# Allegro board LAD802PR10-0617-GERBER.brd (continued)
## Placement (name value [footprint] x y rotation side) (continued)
RW1  0_0402_5%  [R_0402]  44.47 97.82 270 bottom
RW2  0_0402_5%  [R_0402]  43.58 97.82 270 bottom
RW3  0_0805_5%  [R_0805]  60.34 107.62 270 top
RW4  0_0402_5%  [R0402_0OHM]  55.84 109.64 270 top
RW5  0_0805_5%  [R_0805]  60.22 116.05 270 top
RW6  0_0402_5%  [R_0402]  53.93 106.37 90 top
RW8  100K_0402_5%  [R_0402]  52.14 107.21 0 top
RW9  0_0402_5%  [R0402_0OHM]  57.11 97.3 90 bottom
RX1  10K_0402_5%  [R_0402]  222.46 53.06 270 top
RX2  10K_0402_5%  [R_0402]  221.57 53.06 270 top
RX3  100K_0402_5%  [R_0402]  220.68 52.14 90 top
RX4  0_0402_5%  [R_0402-NPM]  219.12 42.95 90 bottom
RX5  4.99K_0402_1%  [R_0402]  208.44 38.06 180 bottom
RX6  0_0402_5%  [R_0402]  216.49 38.45 270 bottom
RX7  0_0402_5%  [R_0402-NPM]  218.23 42.95 90 bottom
RX8  0_0402_5%  [R_0402-NPM]  216.35 42.92 90 bottom
RX9  0_0402_5%  [R_0402-NPM]  217.24 42.92 90 bottom
RX10  10K_0402_5%  [R_0402]  218.45 45.93 90 top
RX11  3.3K_0402_5%  [R_0402]  210.27 36.52 90 bottom
RX12  0_0402_5%  [R_0402]  210.27 39.6 270 top
RX13  10K_0402_5%  [R_0402]  217.53 45.93 90 top
RX14  3.3K_0402_5%  [R_0402]  215.35 45.88 270 bottom
RX15  0_0402_5%  [R_0402]  215.35 45.88 270 top
RX16  4.7K_0402_5%  [R_0402]  211.79 45.88 270 bottom
RX17  4.7K_0402_5%  [R_0402]  211.79 45.88 270 top
RX18  4.7K_0402_5%  [R_0402]  211.16 36.52 90 bottom
RX19  4.7K_0402_5%  [R_0402]  211.16 39.6 270 top
RX20  4.7K_0402_5%  [R_0402]  212.68 45.88 270 bottom
RX21  4.7K_0402_5%  [R_0402]  212.68 45.88 270 top
RX22  4.7K_0402_5%  [R_0402]  213.57 45.88 270 bottom
RX23  4.7K_0402_5%  [R_0402]  213.57 45.88 270 top
RX24  4.7K_0402_5%  [R_0402]  214.46 45.88 270 bottom
RX25  4.7K_0402_5%  [R_0402]  214.46 45.88 270 top
RX26  4.7K_0402_5%  [R_0402]  212.05 36.52 90 bottom
RX27  4.7K_0402_5%  [R_0402]  212.05 39.6 270 top
RX28  4.7K_0402_5%  [R_0402]  212.93 36.52 90 bottom
RX29  4.7K_0402_5%  [R_0402]  212.93 39.6 270 top
RX30  4.7K_0402_5%  [R_0402]  213.82 36.52 90 bottom
RX31  4.7K_0402_5%  [R_0402]  213.82 39.6 270 top
RZ1  22.1K_0402_1%  [R_0402]  136.11 38.04 180 top
RZ2  0_0402_5%  [R_0402]  138.12 31.45 0 top
RZ3  49.9K_0402_1%  [R_0402]  139.15 35.05 90 top
RZ4  0_0603_5%  [R_0603]  135.11 43.52 180 top
RZ9  1M_0402_1%  [R_0402]  138.18 38.51 270 top
SW1  TST71-N-220-T170-S017_2P  [SW_TST71-N-220-T170-S017_2P]  155.1 111.08 180 top
TL1  NS14-1 LF 10/100 BASE-TX  [MHPC_NS681677_12P]  28.02 114.64 270 bottom
TP1  PAD  [TPC12]  119.08 59.39 0 top
TP2  PAD  [TPC12]  118.77 60.66 0 top
TP3  PAD  [TPC12]  95.97 67.14 180 bottom
TP4  PAD  [TPC12]  96.86 68.09 180 bottom
TP5  PAD  [TPC12]  106.57 64.53 0 top
TP6  PAD  [TPC12]  105.24 64.54 0 top
TP7  PAD  [TPC12]  126.96 78.63 180 bottom
TP8  PAD  [TPC12]  120.1 58.11 0 top
TP9  PAD  [TPC12]  121.75 57.55 0 top
TP10  PAD  [TPC12]  103.97 41.74 0 top
TP11  PAD  [TPC12]  95.97 42.44 180 bottom
TP12  PAD  [TPC12]  103.78 40.34 0 top
TP13  PAD  [TPC12]  107.21 38.93 0 top
TP14  PAD  [TPC12]  128.1 68.92 180 bottom
TP15  PAD  [TPC12]  125.88 64.66 180 bottom
TP16  PAD  [TPC12]  126.39 63.45 180 bottom
TP17  PAD  [TPC12]  124.99 63.45 180 bottom
TP18  PAD  [TPC12]  127.15 64.72 180 bottom
TP19  PAD  [TPC12]  99.94 77.15 180 bottom
TP20  PAD  [TPC12]  98.95 77.96 180 bottom
TP21  PAD  [TPC12]  97.3 76.21 180 bottom
TP22  PAD  [TPC12]  97.75 77.49 180 bottom
TP23  PAD  [TPC12]  107.97 39.96 0 top
TP24  PAD  [TPC12]  109.11 39.39 0 top
TP25  PAD  [TPC12]  105.18 36.02 0 top
TP26  PAD  [TPC12]  105.81 34.88 0 top
TP27  PAD  [TPC12]  97.87 31.77 180 bottom
TP28  PAD  [TPC12]  101.56 36.02 0 top
TP29  PAD  [TPC12]  100.86 34.44 0 top
TP30  PAD  [TPC12]  100.1 79.08 180 bottom
TP31  PAD  [TPC12]  98.8 79.35 180 bottom
TP32  PAD  [TPC12]  118.51 51.76 0 top
TP33  PAD  [TPC12]  108.16 51.76 0 top
TP34  PAD  [TPC12]  111.91 71.01 0 top
TP35  PAD  [TPC12]  111.91 69.66 0 top
TP36  PAD  [TPC12]  107.78 68.47 0 top
TP37  PAD  [TPC12]  108.35 66.95 0 top
TP38  PAD  [TPC12]  107.21 47.17 0 top
TP39  PAD  [TPC12]  107.34 45.42 0 top
TP40  PAD  [TPC12]  62.25 45.17 0 top
TP41  PAD  [TPC12]  64.16 44.09 0 top
TP42  PAD  [TPC12]  51.96 43.96 0 top
TP43  PAD  [TPC12]  46.69 45.8 0 top
TP44  PAD  [TPC12]  136.48 24.5 90 bottom
TP46  PAD  [TPC12]  200.3 46.06 180 bottom
TP47  PAD  [TPC12]  194.46 45.8 180 bottom
TP48  PAD  [TPC12]  38.18 117.24 180 bottom
TP49  PAD  [TPC12]  36.47 119.91 180 bottom
TP71  PAD  [TPC12]  157.75 18.05 180 bottom
TP74  PAD  [TPC12]  81.17 17.1 0 top
TP75  PAD  [TPC12]  106.76 41.55 0 top
TPC1  PAD  [TPC12]  128.35 65.17 270 bottom
TPC2  PAD  [TPC12]  125.56 67.07 180 bottom
TPC3  PAD  [TPC12]  129.69 65.17 180 bottom
TPC4  PAD  [TPC12]  126.77 65.99 180 bottom
TPC5  PAD  [TPC12]  121.97 66.76 0 top
TPC6  PAD  [TPC12]  125.62 68.41 180 bottom
TPC7  PAD  [TPC12]  127.15 31.96 180 bottom
TPC8  PAD  [TPC12]  99.84 28.28 180 bottom
TPC9  PAD  [TPC12]  102.32 28.21 180 bottom
TPC10  PAD  [TPC12]  126.31 77.31 180 bottom
TPC11  PAD  [TPC12]  124.94 77.28 180 bottom
TPC12  PAD  [TPC12]  126.49 76.01 180 bottom
TPC13  PAD  [TPC12]  125.94 79.46 180 bottom
TPC14  PAD  [TPC12]  120.73 76.79 0 top
TPC15  PAD  [TPC12]  122.88 77.22 180 bottom
TPC16  PAD  [TPC12]  123.35 79.55 180 bottom
TPC17  PAD  [TPC12]  124.63 79.46 180 bottom
TPC18  PAD  [TPC12]  119.59 70.19 0 top
TPC19  PAD  [TPC12]  120.99 70.12 0 top
TPC20  PAD  [TPC12]  122.47 78.44 180 bottom
TPC21  PAD  [TPC12]  120.58 79.52 180 bottom
TPC22  PAD  [TPC12]  121.61 77.07 180 bottom
TPC23  PAD  [TPC12]  121.93 79.63 180 bottom
TPC24  PAD  [TPC12]  119.65 78.5 180 bottom
TPC25  PAD  [TPC12]  120.9 78.19 180 bottom
TPC26  PAD  [TPC12]  119.82 75.82 180 bottom
TPC27  PAD  [TPC12]  120.24 77.06 180 bottom
TPC28  PAD  [TPC12]  120.1 72.33 0 top
TPC29  PAD  [TPC12]  121.56 72.28 0 top
TPC30  PAD  [TPC12]  129.56 68.78 180 bottom
TPC31  PAD  [TPC12]  124.86 65.99 180 bottom
TPC32  PAD  [TPC12]  80.6 29.74 0 top
TPC33  PAD  [TPC12]  130 79.33 180 bottom
TPS1  PAD  [TPC12]  123.21 28.02 180 bottom
TPS2  PAD  [TPC12]  105.75 40.28 0 top
TPS3  PAD  [TPC12]  136.67 27.01 0 top
TPS4  PAD  [TPC12]  98.45 41.74 180 bottom
TPS5  PAD  [TPC12]  97.11 41.67 180 bottom
TPS6  PAD  [TPC12]  105.53 43.46 0 top
TPS7  PAD  [TPC12]  90.06 24.47 0 top
TPS8  PAD  [TPC12]  153.27 109.24 0 top
TPS9  PAD  [TPC12]  152.25 104.31 0 top
TPS10  PAD  [TPC12]  132.48 39.2 180 bottom
U1  -  [SY6288C20AAC_SOT23-5]  224.84 26.38 0 bottom
U2  -  [NCT7718W_MSOP8]  112.22 107.46 90 bottom
UA1  ALC3246-CG_MQFN48_6X6  [ALC3246-CG_MQFN48_6X6-S]  29.59 23.01 270 top
UC1  SKL-U_BGA1356  [SKL-U_BGA_1356P-T]  123.48 33.54 270 bottom
UC2  -  [74AUP1G07GW_TSSOP5]  90.94 79.06 0 top
UC3  -  [W25Q128FVSIQ_SO8]  117.69 20.07 270 bottom
UC4  -  [SN74AHC1G08DCKR_SC70-5]  108.31 19.38 180 bottom
UC5  -  [SN74AHC1G08DCKR_SC70-5]  83.51 21.02 0 top
UC6  -  [74AUP1G07GW_TSSOP5]  88.14 19.17 270 top
UC7  -  [74AUP1G07GW_TSSOP5]  133.26 76.91 180 top
UC9  -  [SN74AHC1G08DCKR_SC70-5]  136.91 28.07 0 top
UE1  -  [MEC1404-NU-TR_VTQFP128_14X14]  140.33 18.78 0 bottom
UE2  -  [SN74LVC1G06DCKR_SC70-5]  153.6 22.84 180 top
UL1  RTL8106E-CG_QFN32_4X4  [RTL8106E-CG_QFN32_4X4-S]  36.15 114.73 180 bottom
UL3  -  [SY6288C20AAC_SOT23-5]  28.65 120.81 180 bottom
UU1  -  [SY6288D20AAC_SOT23-5]  8.58 27.39 270 bottom
UU3  -  [SY6288D20AAC_SOT23-5]  169.39 20.14 270 bottom
UX1  TPS22967DSGR_SON8_2X2  [TPS22967DSGR_SON8_2X2-S]  219.11 50.07 90 top
UX2  PS8713BTQFN24GTR2-A0_TQFN24_4X4  [SN65LVPE502CPRGER_VQFN24_4X4-S]  213.99 39.07 180 bottom
UZ1  TPS22967DSGR_SON8_2X2  [TPS22967DSGR_SON8_2X2-S]  132.81 37.52 0 top
UZ2  -  [TPS22961DNYR_WSON8]  137.07 33.45 90 top
UZ3  EM5209VF_DFN14_3X2  [EM5209VF_DFN14_3X2-S]  168.58 24.16 180 top
YC1  24MHZ_12PF_X3G024000DC1H  [Y_X3G024000DC1H_4P]  132.46 52.06 90 bottom
YC2  32.768KHZ_9PF_X1A000141000200  [Y_X1A000141000200_2P]  92.26 30.74 180 top
YE1  32.768KHZ_9PF_X1A000141000200  [Y_X1A000141000200_2P]  144.09 12.48 180 bottom
YL1  25MHZ_10PF_7V25000014  [Y_7V25000014_4P]  37.97 122.41 0 bottom
ZT1  PAD  [TPC12]  156.45 111.42 0 top
ZT2  PAD  [TPC12]  156.73 109.56 0 top
ZT3  PAD  [TPC12]  156.85 107.93 0 top
ZT4  PAD  [TPC12]  12.53 8.13 0 top
ZT5  PAD  [TPC12]  10.84 8.12 0 top
ZT6  PAD  [TPC12]  11.22 4.92 0 top
ZT7  PAD  [TPC12]  8.86 5.31 0 top
ZT8  PAD  [TPC12]  105.8 10.2 0 top
ZT9  PAD  [TPC12]  108.29 5.99 0 top
ZT10  PAD  [TPC12]  99.05 7.31 0 top
ZT11  PAD  [TPC12]  102.95 11.45 0 top
ZT12  PAD  [TPC12]  98.04 14.32 0 top
ZT13  PAD  [TPC12]  96.67 11.45 180 bottom
ZT14  PAD  [TPC12]  148.99 31.26 0 top
ZT15  PAD  [TPC12]  145.69 30.75 0 top
ZT16  PAD  [TPC12]  151.28 11.96 0 top
ZT17  PAD  [TPC12]  151.92 13.73 0 top
ZT18  PAD  [TPC12]  15.55 15.99 0 top
ZT19  PAD  [TPC12]  14.55 11.07 0 top
ZT20  PAD  [TPC12]  14.05 21.29 180 bottom
ZT21  PAD  [TPC12]  14.31 23.64 180 bottom
ZT22  PAD  [TPC12]  14.66 12.64 0 top
ZT23  PAD  [TPC12]  12.28 11.64 180 bottom
ZT24  PAD  [TPC12]  63.34 10.56 0 top
ZT25  PAD  [TPC12]  64.85 9.7 0 top
ZT26  PAD  [TPC12]  65.41 7.31 0 top
ZT27  PAD  [TPC12]  67.06 9.81 0 top
ZT28  PAD  [TPC12]  67.05 7.28 0 top
ZT29  PAD  [TPC12]  68.64 9.17 0 top
ZT30  PAD  [TPC12]  70.37 8.79 0 top
ZT31  PAD  [TPC12]  71.2 10.53 0 top
ZT32  PAD  [TPC12]  68.84 7.31 0 top
ZT33  PAD  [TPC12]  71.65 7.24 0 top
ZT34  PAD  [TPC12]  73.02 9.61 0 top
ZT35  PAD  [TPC12]  73.59 7.12 0 top
ZT36  PAD  [TPC12]  74.21 10.99 0 top
ZT37  PAD  [TPC12]  75.13 8.83 0 top
ZT38  PAD  [TPC12]  75.75 11.69 0 top
ZT39  PAD  [TPC12]  76.88 9.28 0 top
ZT40  PAD  [TPC12]  77.36 11.13 0 top
ZT41  PAD  [TPC12]  77.06 7.36 0 top
ZT42  PAD  [TPC12]  79.2 10.77 0 top
ZT43  PAD  [TPC12]  80.33 12.45 0 top
ZT44  PAD  [TPC12]  80.56 9.06 0 top
ZT45  PAD  [TPC12]  81.92 11.21 0 top
ZT46  PAD  [TPC12]  82.4 8.77 0 top
ZT47  PAD  [TPC12]  84.09 11.4 0 top
ZT48  PAD  [TPC12]  84.06 9.48 0 top
ZT49  PAD  [TPC12]  85.82 10.6 0 top
ZT50  PAD  [TPC12]  84.28 7.77 0 top
ZT51  PAD  [TPC12]  116.61 10.05 180 bottom
ZT52  PAD  [TPC12]  114.45 4.53 0 top
ZT53  PAD  [TPC12]  128.42 9.16 0 top
ZT54  PAD  [TPC12]  129.56 9.73 0 top
ZT55  PAD  [TPC12]  129.43 12.88 0 top
ZT56  PAD  [TPC12]  130.89 9.73 0 top
ZT57  PAD  [TPC12]  135.59 9.23 0 top
ZT58  PAD  [TPC12]  134.7 10.43 0 top
ZT59  PAD  [TPC12]  93.05 9.29 180 bottom
ZT60  PAD  [TPC12]  126.89 9.16 0 top
ZT61  PAD  [TPC12]  120.86 9.48 180 bottom
ZT62  PAD  [TPC12]  28.02 81.45 0 top
ZT63  PAD  [TPC12]  58.36 98.21 180 bottom

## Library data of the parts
C1-C3 C5-C11 C13 C14 C16-C19 C21 C23-C27 C32-C34 CA2 CA4 CA6 CA7 CA10 CA14 CA16 CA17 CA27-CA31 CA34-CA37 CC1-CC35 CC39-CC58 CC60-CC73 CC75 CC78 CC79 CC82 CC85-CC90 CD3-CD5 CD9 CD11-CD18 CD28-CD31 CD35 CD36 CD39 CD41-CD48 CD58 CD59 CE1-CE4 CE6-CE23 CE25-CE33 CI1-CI9 CL1-CL6 CL8-CL12 CL14 CS1-CS6 CS9-CS14 CS16-CS19 CU1-CU7 CU17-CU19 CW1-CW4 CW7-CW9 CX1-CX13 CZ1-CZ12 CZ21-CZ25 EC2201-EC2216 EC2225 EC2226 EC2229 EC2230 EC2301 EC2302 EC2901 EC2902 EC3001 EC3002 EC3201 EC3202 PC1-PC4 PC7 PC8 PC14 PC16 PC100 PC102 PC103 PC113-PC116 PC127 PC128 PC130-PC133 PC200-PC203 PC207 PC208 PC210 PC213 PC214 PC230 PC231 PC301 PC302 PC304-PC307 PC309 PC320 PC321 PC502-PC504 PC601 PC602 PC605 PC611 PC613 PC614 PC616-PC621 PC624-PC633 PC635-PC647 PC649-PC655 PC659-PC661 PC663 PC666-PC669 PC671 PC674 PC677 PC679-PC681 PC685-PC688 PC691-PC695 PC705 PC708 PC711 PC721 PC742 PC744 PC747-PC749 PC751-PC753 PC765 PC768 PC769 PC777 PC779-PC781 PC790 PC801 PC803 PC805 PC1201 PC1202 PC1204 PC1205 PC1209-PC1212 = C_0402
C4 C15 C20 C22 CA1 CA3 CA5 CA11-CA13 CA15 CA20-CA26 CA32 CA33 CC36-CC38 CC76 CC77 CC80 CC81 CC83 CC84 CD1 CD2 CD6-CD8 CD10 CD19-CD26 CD32-CD34 CD37 CD38 CD40 CD49-CD56 CE5 CE24 CL7 CW5 CW6 EC2217 EC2218 PC111 PC112 PC119 PC125 PC126 PC204 PC209 PC215-PC220 PC308 PC310-PC313 PC501 PC505-PC507 PC603 PC604 PC622 PC662 PC670 PC678 PC750 PC757 PC767 PC1001-PC1029 PC1057-PC1061 PC1064-PC1082 PC1129-PC1146 PC1154-PC1156 PC1158 PC1159 PC1161-PC1163 PC1170-PC1184 PC1203 PC1206-PC1208 PC1221-PC1224 = C_0603
C30 CC59 CC74 CS7 CS15 CU8 CU9 CU20 CU21 PC104-PC110 PC117 PC118 PC120-PC124 PC205 PC206 PC211 PC212 PC303 PC608 PC612 PC656-PC658 PC664 PC665 PC672 PC673 PC760-PC764 PC766 PC775 PC776 PC778 PC802 PC804 = C_0805
CD27 CD57 = C_D2
CL13 CU10 CU22 = C_1206
D1 = BAS40C_SOT23-3
D2 D5 D6 = RB551V-30_SOD323-2
D3 D4 DA3 = BAT54C-7-F_SOT23-3
D8 PD102 = SDMK0340L-7-F_SOD323-2
DA1 DA2 = AZ5125-02SPR7G_SOT23-3
DA4 = L03ESDL5V0CC3-2_SOT23-3
DA5 = AZ5123-02SPR7G_SOT23-3
DA6 = PESD5V0U2BT_SOT23-3
DE1 = AZ5125-01HPR7G_SOD523-2
DX1 = IP4292CZ10-TBR_XSON10_2P5X1
DX2 DX3 DZ1-DZ5 = RB751S40T1G_SOD523-2
ED2901 = AZ5725-01F_DFN2
EU2601 EU2603 EU3101 = L05ESDL5V0NA-4_SLP2510P8-10-9
EU2602 EU2604 = AZC199-02SPR7G_SOT23-3
EU3501 = TVWDF1004AD0_DFN9
F1 F2 = F_SMD1812P110TF-24
F3 = F_MF-NSMF050-2
FD1-FD4 = FIDUCIAL_C40M80
FI1 = F_1206L150PR
H1-H5 H21 = H_3P0-G
H6 = H_5P6N
H7 = H_3P0N
H11 = H_3P2
H12 = H_3P2X2P6
HCPU1 HCPU4 = H_3P7X4P3
HCPU2 = H_3P9
HCPU3 = H_3P7
J3D1 = ACES_50463-0104A-001_10P
JCMOS1 = SHORTPADS: User Part Number: PART#
JDB1 JDEG1 = JXT_FP241AH-010GAAM_10P
JDIMM1 = DEREN_40-42271-26001RHF_260P-T
JDIMM2 = DEREN_40-42261-26001RHF_260P-T
JEDP1 = ACES_51540-04001-P01_40P
JFAN1 JSPK1 = JXT_WB247H-004S10M_4P
JHDD1 = ACES_51625-01201-001_12P
JHDMI1 = CONCR_099AKAC19NBLCNF_19P
JHP1 = YUQIU_PJ753-F07J1BE-B_7P-T
JIOB1 = ACES_51524-0160N-001_16P
JKB1 = STARC_132C30-100020-A2-R_30P
JKBBL1 = ACES_51575-00401-001_4P-T
JLAN1 = SANTA_130460-N_8P-T
JLED1 = ACES_51524-0040N-001_4P
JODD1 = ACES_50673-0120N-001_12P-T
JP1 JP9 JP12 JP13 PJP105 PJP106 PJP203 PJP206 PJP301 PJP501 PJP502 PJP801 PJP802 PJP1201 PJP1202 = JUMP_43X79
JP2 JP3 JP10 JP11 PJP603 = JUMP_43X39
JP4 JP5 PJP102 PJP103 PJP200 PJP302 PJP602 PJP701 = JUMP_43X118
JPWR1 = JXT_FP226H-006S1BM_6P
JRTC1 = ACES_50271-0020N-001_2P
JSSD1 = ACES_50406-03071-001_30P
JTP1 = JXT_FP202DH-008M10M_8P
JUSB1 JUSB2 = ACON_TARA4-9K1311_9P
JWLAN1 = LCN_DAN05-67406-0100_67P
L1 L2 = MURAT_BLM15BD601SN1D_2P
L3 LU1 LU4 LU7 LU8 = INPAQ_MCM1012B900F06BP_4P
L4 LW1 = INPAQ_MCM1012B900F06BP_4P-NPM
L5 = MURAT_BLM15PX221SN1D_2P
LI1-LI4 LU2 LU3 LU5 LU6 = INPAQ_HCM1012GH900BP_4P-NPM
LX1 LX2 = TAIYO_MCF12102G900-T_4P
PBATT1 = ACES_50458-01001-P01_10P-T
PC606 PC690 = C_25CL33LD
PC1030-PC1056 PC1083-PC1099 PC1125 PC1126 PC1147-PC1153 PC1164 = C_0201
PC1062 PC1063 PC1101 PC1127 PC1128 = C_5X4P5
PD2-PD4 = TVNST52302AB0_SOT523-3
PD5 PD6 = BAV99W_SC70-3
PD704 = LRB715FT1G_SOT323-3
PH601-PH605 PR2-PR4 PR6-PR13 PR15 PR16 PR18 PR20 PR28 PR29 PR31-PR33 PR102 PR103 PR107-PR110 PR113-PR115 PR117 PR118 PR122 PR204 PR205 PR207-PR209 PR302 PR305 PR308-PR310 PR502-PR505 PR601 PR604 PR605 PR608 PR610-PR613 PR615 PR617 PR618 PR621-PR623 PR626 PR628-PR654 PR656 PR657 PR662 PR664 PR666 PR668 PR670 PR673 PR675 PR677 PR678 PR680 PR681 PR727 PR729 PR731 PR732 PR737 PR738 PR740-PR742 PR745 PR749-PR757 PR760 PR762-PR764 PR774 PR777 PR781 PR790 PR791 PR801 PR802 PR1201 PR1202 PR1204-PR1207 R1 R2 R5 R6 R9 R10 R19-R35 R38-R43 R45-R50 R53 R56 R57 RA3 RA7-RA12 RA23-RA34 RA41 RA42 RC1-RC16 RC18-RC47 RC51-RC70 RC72-RC78 RC80-RC82 RC84-RC96 RC100 RC102-RC105 RC108-RC115 RC117-RC134 RC136-RC148 RC150-RC160 RC164 RC175-RC182 RC187-RC189 RC192 RD1-RD3 RD7 RD9-RD13 RD15 RD17 RD19-RD24 RE1 RE3 RE4 RE6 RE8-RE21 RE23-RE27 RE29 RE30 RE32-RE35 RE38 RE40 RE41 RE43-RE49 RE51-RE59 RI1-RI16 RL1-RL4 RL6 RL7 RL16 RS1 RU3-RU6 RU9-RU12 RW1 RW2 RW6 RW8 RX1-RX3 RX5 RX6 RX10-RX31 RZ1-RZ3 RZ9 = R_0402
PJP1-PJP3 = JUMP_43X79-NPM
PJP601 = JUMP_43X118-NPM
PJPDC1 = ACES_50458-00601-001_6P-T
PL1 PL3 PL4 PL602 = 5A_Z150_1210_2P
PL2 = MURAT_BLM15AG102SN1D_2P
PL100 PL101 PL200 PL700 = L_7X7X3_M_2P
PL102 PL103 PL201 PL302 PL606 PL1202 = 5A_Z150_1210_2P-NPM
PL301 PL501 PL1201 = L_5X5X3_M_2P
PL601 = L_5X5X3_M
PL603-PL605 = L_7X7X4_M
PL704 = L_5X5X3_M_2P-NPM
PQ1 PQ2 = 2N7002DW-T-R7_SOT363-6
PQ3 PQ709 PQ712 = L2N7002WT1G_SC70-3
PQ5 = RHU002N06_SOT323-3
PQ6 = FDV301N_NL_SOT23-3
PQ201 PQ601 = AON7934_DFN3X3A8-10
PQ704 PQ708 = SIS412DN-T1-GE3_POWERPAK8-5
PQ710 = LMUN5113T1G_SOT323-3
PQ711 = LTC015EUBFS8TL_UMT3F
PQ717 PQ718 PQ740 = MDU1512RH_POWERDFN56-8-5
PQ720 PQ721 = RUM002N02GT2L_VMT3
PR5 PR106 PR112 PR203 PR307 PR506 PR627 PR663 PR669 PR676 PR743 PR766 PR1208 = R_1206
PR100 PR111 PR200 PR306 PR761 PR771 PR773 R55 RA4 RA39 RC17 RC161-RC163 RC169-RC171 RC173 RC174 RE2 RE7 RE50 RL5 = R0603_0OHM
PR116 PR120 PR121 PR201 PR202 PR301 PR303 PR304 PR501 PR602 PR603 PR606 PR607 PR609 PR616 PR620 PR625 PR655 PR659 PR671 PR679 PR769 PR770 PR772 PR775 PR776 PR778 PR779 PR803 R8 RA2 RA5 RA6 RA17 RA18 RA36 RA37 RA40 RC83 RC97 RC99 RC106 RC107 RD4-RD6 RD8 RD14 RD16 RD18 RE22 RE28 RE37 RE42 RE60 RE61 RE63 RE64 RL12 RL13 RW4 RW9 = R0402_0OHM
PR206 PR210 PR619 PR624 PR660 PR661 PR665 PR667 PR672 PR674 PR780 PR1203 R11-R13 R16 R36 R37 R44 RC149 RL14 RL15 RZ4 = R_0603
PR703 PR765 = R_1206_4P
PU100 = SY8286BRAC_QFN20_3X3-S
PU102 = SY8286CRAC_QFN20_3X3-S
PU200 = RT8207PGQW_WQFN20_3X3-S
PU300 = SY8286RAC_QFN20_3X3-S
PU500 = SY8033BDBC_DFN10_3X3-S
PU602 = ISL62883CHRTZ-T_TQFN40_5X5-S
PU603-PU605 = AOZ5019QI_QFN23_5X3P5
PU606 = ISL95808HRZ-TS2378_DFN8_2X2-S
PU703 = ISL95520HRZ-T_QFN32_4X4-S
PU800 = RT904225GSP_SO8
PU1200 = NB681GD-Z_QFN13_2X3
Q1 Q5 Q12 Q13 QC2 QI1 = 2N7002K_SOT23-3
Q2 Q10 Q11 QC1 QI2 = DMN66D0LDW-7_SOT363-6
Q3 Q4 Q7 Q15 = DDTA144VCA-7-F_SOT23-3
Q6 Q8 Q9 Q16 QA1 = LN2306LT1G_SOT23-3
Q14 = LMBT3904LT1G_SOT23-3
QI3 = SSM3K7002FU_SC70-3
R3 R54 RW3 RW5 = R_0805
R17 R18 RU1 RU2 RU7 RU8 RU13-RU16 RX4 RX7-RX9 = R_0402-NPM
R51 RA1 RA22 = R0805_0OHM
RA13-RA16 = MURAT_BLM15PD600SN1D_2P
RA35 RA38 = MURAT_BLM15PX330SN1D_2P
RP1 RP2 RPC1 RPE1-RPE6 RPI1 RPI2 = RP_0804_8P4R
SW1 = SW_TST71-N-220-T170-S017_2P
TL1 = MHPC_NS681677_12P
TP1-TP44 TP46-TP49 TP71 TP74 TP75 TPC1-TPC33 TPS1-TPS10 ZT1-ZT63 = TPC12
U1 UL3 = SY6288C20AAC_SOT23-5
U2 = NCT7718W_MSOP8
UA1 = ALC3246-CG_MQFN48_6X6-S
UC1 = SKL-U_BGA_1356P-T
UC2 UC6 UC7 = 74AUP1G07GW_TSSOP5
UC3 = W25Q128FVSIQ_SO8
UC4 UC5 UC9 = SN74AHC1G08DCKR_SC70-5
UE1 = MEC1404-NU-TR_VTQFP128_14X14
UE2 = SN74LVC1G06DCKR_SC70-5
UL1 = RTL8106E-CG_QFN32_4X4-S
UU1 UU3 = SY6288D20AAC_SOT23-5
UX1 UZ1 = TPS22967DSGR_SON8_2X2-S
UX2 = SN65LVPE502CPRGER_VQFN24_4X4-S
UZ2 = TPS22961DNYR_WSON8
UZ3 = EM5209VF_DFN14_3X2-S
YC1 = Y_X3G024000DC1H_4P
YC2 YE1 = Y_X1A000141000200_2P
YL1 = Y_7V25000014_4P

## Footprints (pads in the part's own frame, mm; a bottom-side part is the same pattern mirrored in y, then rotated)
2N7002DW-T-R7_SOT363-6
  oval 0.381x1.397 smd: 1(0,0) 2(0.65,0) 3(1.3,0) 4(1.3,1.725) 5(0.65,1.725) 6(0,1.725)
2N7002K_SOT23-3
  oval 1.016x1.524 smd: 1(0,0) 2(0.965,2.083) 3(-0.965,2.083)
5A_Z150_1210_2P
  rect 0.991x2.997 smd: 1(0,0) 2(2.7,0)
5A_Z150_1210_2P-NPM
  rect 0.991x2.997 smd: 1(0,0) 2(2.7,0)
74AUP1G07GW_TSSOP5
  oval 0.381x1.346 smd: 1(0,0) 2(0.65,0) 3(1.3,0) 4(1.3,1.79) 5(0,1.79)
ACES_50271-0020N-001_2P
  oval 0.787x1.6 smd: 1(0,0) 2(1.25,0)
  rect 2.108x2.997 smd: 3(3.8,-2.9) 4(-2.55,-2.9)
ACES_50406-03071-001_30P
  oval 0.254x1.295 smd: 1(0,0) 2(0.5,0) 3(1,0) 4(1.5,0) 5(2,0) 6(2.5,0) 7(3,0) 8(3.5,0) 9(4,0) 10(4.5,0) 11(5,0) 12(5.5,0) 13(6,0) 14(6.5,0) 15(7,0) 16(7.5,0) 17(8,0) 18(8.5,0) 19(9,0) 20(9.5,0) 21(10,0) 22(10.5,0) 23(11,0) 24(11.5,0) 25(12,0) 26(12.5,0) 27(13,0) 28(13.5,0) 29(14,0) 30(14.5,0)
  rect 1.194x2.692 smd: 31(16.9,1.95) 35(-2.4,1.95)
  rect 2.311x1.295 smd: 32(13.65,3.9) 33(7.25,3.9) 34(0.85,3.9)
ACES_50458-00601-001_6P-T
  oval 0.559x1.6 smd: 1(0,0) 2(2,0) 3(4,0) 4(6,0) 5(8,0) 6(10,0)
  rect 1.295x2.057 smd: 7(-3.1,-5.175) 8(13.1,-5.175)
ACES_50458-01001-P01_10P-T
  oval 0.559x1.803 smd: 1(0,0) 2(2,0) 3(4,0) 4(6,0) 5(8,0) 6(10,0) 7(12,0) 8(14,0) 9(16,0) 10(18,0)
  rect 1.295x2.057 smd: 11(-3.1,-5.275) 12(21.1,-5.275)
ACES_50463-0104A-001_10P
  oval 0.203x1.194 smd: 1(0,0) 2(-0.4,0) 3(-0.8,0) 4(-1.2,0) 5(-1.6,0) 6(-2,0) 7(-2.4,0) 8(-2.8,0) 9(-3.2,0) 10(-3.6,0)
  rect 0.889x2.007 smd: 11(-5.85,-1.37) 12(2.25,-1.37)
ACES_50673-0120N-001_12P-T
  oval 0.61x1.499 smd: 1(0,0) 3(-1,0) 5(-2,0) 7(-3,0) 9(-4,0) 11(-5,0) 13(-6,0) 15(-7,0) 17(-8,0) 19(-9,0) 21(-10,0) 23(-11,0)
  oval 0.61x1.194 smd: 2(0,2.85) 4(-1,2.85) 6(-2,2.85) 8(-3,2.85) 10(-4,2.85) 12(-5,2.85) 14(-6,2.85) 16(-7,2.85) 18(-8,2.85) 20(-9,2.85) 22(-10,2.85) 24(-11,2.85)
  rect 1.702x2.311 smd: 25(-13.25,1.425) 26(2.25,1.425)
ACES_51524-0040N-001_4P
  oval 0.61x1.448 smd: 1(0,0) 2(1,0) 3(2,0) 4(3,0)
  rect 2.489x2.21 smd: 5(-3,-3.125) 6(6,-3.125)
ACES_51524-0160N-001_16P
  oval 0.61x1.295 smd: 1(0,0) 2(1,0) 3(2,0) 4(3,0) 5(4,0) 6(5,0) 7(6,0) 8(7,0) 9(8,0) 10(9,0) 11(10,0) 12(11,0) 13(12,0) 14(13,0) 15(14,0) 16(15,0)
  rect 2.159x2.21 smd: 17(-2.825,-3.05) 18(17.825,-3.05)
ACES_51540-04001-P01_40P
  oval 0.305x1.092 smd: 1(0,0) 2(0.5,0) 3(1,0) 4(1.5,0) 5(2,0) 6(2.5,0) 7(3,0) 8(3.5,0) 9(4,0) 10(4.5,0) 11(5,0) 12(5.5,0) 13(6,0) 14(6.5,0) 15(7,0) 16(7.5,0) 17(8,0) 18(8.5,0) 19(9,0) 20(9.5,0) 21(10,0) 22(10.5,0) 23(11,0) 24(11.5,0) 25(12,0) 26(12.5,0) 27(13,0) 28(13.5,0) 29(14,0) 30(14.5,0) 31(15,0) 32(15.5,0) 33(16,0) 34(16.5,0) 35(17,0) 36(17.5,0) 37(18,0) 38(18.5,0) 39(19,0) 40(19.5,0)
  rect 0.787x2.489 smd: 41(21.2,-3.6) 42(-1.7,-3.6)
ACES_51575-00401-001_4P-T
  oval 0.406x1.194 smd: 1(0,0) 2(1,0) 3(2,0) 4(3,0)
  rect 0.787x2.007 smd: 5(-2.2,-3.4) 6(5.2,-3.4)
ACES_51625-01201-001_12P
  oval 0.305x1.092 smd: 1(0,0) 2(0.5,0) 3(1,0) 4(1.5,0) 5(2,0) 6(2.5,0) 7(3,0) 8(3.5,0) 9(4,0) 10(4.5,0) 11(5,0) 12(5.5,0)
  rect 0.991x2.489 smd: 13(-1.8,-3.6) 14(7.3,-3.6)
ACON_TARA4-9K1311_9P
  round 1.194 hole 0.711: 1(0,0) 2(-2.5,0) 3(-4.5,0) 4(-7,0) 5(-7.5,-1.5) 6(-5.5,-1.5) 7(-3.5,-1.5) 8(-1.5,-1.5) 9(0.5,-1.5)
  oval 1.397x2.591 hole 0.787x2.007: 10(-11.35,-1.59) 13(4.35,-1.59)
  oval 1.397x2.388 hole 0.787x1.803: 11(-11.35,-9.09) 12(4.35,-9.09)
ALC3246-CG_MQFN48_6X6-S
  oval 0.889x0.203 smd: 1(0,0) 2(0,-0.4) 3(0,-0.8) 4(0,-1.2) 5(0,-1.6) 6(0,-2) 7(0,-2.4) 8(0,-2.8) 9(0,-3.2) 10(0,-3.6) 11(0,-4) 12(0,-4.4) 25(6.1,-4.4) 26(6.1,-4) 27(6.1,-3.6) 28(6.1,-3.2) 29(6.1,-2.8) 30(6.1,-2.4) 31(6.1,-2) 32(6.1,-1.6) 33(6.1,-1.2) 34(6.1,-0.8) 35(6.1,-0.4) 36(6.1,0)
  oval 0.203x0.889 smd: 13(0.85,-5.25) 14(1.25,-5.25) 15(1.65,-5.25) 16(2.05,-5.25) 17(2.45,-5.25) 18(2.85,-5.25) 19(3.25,-5.25) 20(3.65,-5.25) 21(4.05,-5.25) 22(4.45,-5.25) 23(4.85,-5.25) 24(5.25,-5.25) 37(5.25,0.85) 38(4.85,0.85) 39(4.45,0.85) 40(4.05,0.85) 41(3.65,0.85) 42(3.25,0.85) 43(2.85,0.85) 44(2.45,0.85) 45(2.05,0.85) 46(1.65,0.85) 47(1.25,0.85) 48(0.85,0.85)
  rect 4.394x4.394 smd: 49(3.05,-2.2)
AON7934_DFN3X3A8-10
  oval 0.457x0.508 smd: 1(0,0) 2(0.65,0) 3(1.3,0) 4(1.95,0) 5(1.95,2.76) 6(1.3,2.76) 7(0.65,2.76) 8(0,2.76)
  rect 2.54x1.041 smd: 9(0.975,1.813)
  rect 2.54x0.559 smd: 10(0.975,0.708)
AOZ5019QI_QFN23_5X3P5
  oval 0.254x0.762 smd: 1(0,0) 2(0.5,0) 3(1,0) 4(1.5,0) 5(2,0)
  rect 3.175x1.524 smd: 6(1.475,1.335)
  custom 0.588x0.588 smd: 7(1.005,2.425)
  rect 1.956x0.864 smd: 8(1.255,4.787)
  oval 0.762x0.254 smd: 9(-0.67,2.925) 10(-0.67,1.925) 11(-0.67,1.425) 12(-0.67,0.925) 13(-0.67,0.425)
AZ5123-02SPR7G_SOT23-3
  oval 1.016x1.524 smd: 1(0,0) 2(0.965,2.083) 3(-0.965,2.083)
AZ5125-01HPR7G_SOD523-2
  rect 0.61x0.787 smd: 1(0,0) 2(1.5,0)
AZ5125-02SPR7G_SOT23-3
  oval 1.016x1.524 smd: 1(0,0) 2(0.965,2.083) 3(-0.965,2.083)
AZ5725-01F_DFN2
  rect 0.559x0.61 smd: 1(0,0) 2(0.85,0)
AZC199-02SPR7G_SOT23-3
  oval 1.016x1.524 smd: 1(0,0) 2(0.965,2.083) 3(-0.965,2.083)
BAS40C_SOT23-3
  oval 1.016x1.524 smd: 1(0,0) 2(0.965,2.083) 3(-0.965,2.083)
BAT54C-7-F_SOT23-3
  oval 1.016x1.524 smd: 1(0,0) 2(0.965,2.083) 3(-0.965,2.083)
BAV99W_SC70-3
  oval 0.508x0.559 smd: 1(0,0) 2(-0.65,-1.85) 3(0.65,-1.85)
C_5X4P5
  oval 2.997x1.6 smd: 1(0,0) 2(-4.4,0)
C_25CL33LD
  oval 3.607x1.803 smd: 1(0,0) 2(5.4,0)
C_0201
  rect 0.381x0.356 smd: 1(0,0) 2(0.584,0)
C_0402
  rect 0.508x0.559 smd: 1(0,0) 2(0.914,0)
C_0603
  rect 0.635x0.889 smd: 1(0,0) 2(1.397,0)
C_0805
  rect 0.813x1.397 smd: 1(0,0) 2(1.702,0)
C_1206
  rect 1.016x1.651 smd: 1(0,0) 2(2.667,0)
C_D2
  rect 2.388x2.794 smd: 1(0,0) 2(6.4,0)
CONCR_099AKAC19NBLCNF_19P
  round 0.813 hole 0.559: 1(0,0) 2(0.5,1.55) 3(1,0) 4(1.5,1.55) 5(2,0) 6(2.5,1.55) 7(3,0) 8(3.5,1.55) 9(4,0) 10(4.5,1.55) 11(5,0) 12(5.5,1.55) 13(6,0) 14(6.5,1.55) 15(7,0) 16(7.5,1.55) 17(8,0) 18(8.5,1.55) 19(9,0)
  oval 1.499x2.21 hole 0.889x1.6: 20(-2.75,1.7) 21(-4.65,-6.5) 22(11.75,1.7) 23(13.65,-7.75)
DDTA144VCA-7-F_SOT23-3
  oval 1.016x1.524 smd: 1(0,0) 2(0.965,2.083) 3(-0.965,2.083)
DEREN_40-42261-26001RHF_260P-T
  round 1.092 hole 1.092 unplated: (-67.775,-4.1)
  round 1.6 hole 1.6 unplated: (1.025,-4.1)
  oval 0.305x1.753 smd: 1(0,0) 2(-0.25,-8.2) 3(-0.5,0) 4(-0.75,-8.2) 5(-1,0) 6(-1.25,-8.2) 7(-1.5,0) 8(-1.75,-8.2) 9(-2,0) 10(-2.25,-8.2) 11(-2.5,0) 12(-2.75,-8.2) 13(-3,0) 14(-3.25,-8.2) 15(-3.5,0) 16(-3.75,-8.2) 17(-4,0) 18(-4.25,-8.2) 19(-4.5,0) 20(-4.75,-8.2) 21(-5,0) 22(-5.25,-8.2) 23(-5.5,0) 24(-5.75,-8.2) 25(-6,0) 26(-6.25,-8.2) 27(-6.5,0) 28(-6.75,-8.2) 29(-7,0) 30(-7.25,-8.2) 31(-7.5,0) 32(-7.75,-8.2) 33(-8,0) 34(-8.25,-8.2) 35(-8.5,0) 36(-8.75,-8.2) 37(-9,0) 38(-9.25,-8.2) 39(-9.5,0) 40(-9.75,-8.2) 41(-10,0) 42(-10.25,-8.2) 43(-10.5,0) 44(-10.75,-8.2) 45(-11,0) 46(-11.25,-8.2) 47(-11.5,0) 48(-11.75,-8.2) 49(-12,0) 50(-12.25,-8.2) 51(-12.5,0) 52(-12.75,-8.2) 53(-13,0) 54(-13.25,-8.2) 55(-13.5,0) 56(-13.75,-8.2) 57(-14,0) 58(-14.25,-8.2) 59(-14.5,0) 60(-14.75,-8.2) 61(-15,0) 62(-15.25,-8.2) 63(-15.5,0) 64(-15.75,-8.2) 65(-16,0) 66(-16.25,-8.2) 67(-16.5,0) 68(-16.75,-8.2) 69(-17,0) 70(-17.25,-8.2) 71(-17.5,0) 72(-17.75,-8.2) 73(-18,0) 74(-18.25,-8.2) 75(-18.5,0) 76(-18.75,-8.2) 77(-19,0) 78(-19.25,-8.2) 79(-19.5,0) 80(-19.75,-8.2) 81(-20,0) 82(-20.25,-8.2) 83(-20.5,0) 84(-20.75,-8.2) 85(-21,0) 86(-21.25,-8.2) 87(-21.5,0) 88(-21.75,-8.2) 89(-22,0) 90(-22.25,-8.2) 91(-22.5,0) 92(-22.75,-8.2) 93(-23,0) 94(-23.25,-8.2) 95(-23.5,0) 96(-23.75,-8.2) 97(-24,0) 98(-24.25,-8.2) 99(-24.5,0) 100(-24.75,-8.2) 101(-25,0) 102(-25.25,-8.2) 103(-25.5,0) 104(-25.75,-8.2) 105(-26,0) 106(-26.25,-8.2) 107(-26.5,0) 108(-26.75,-8.2) 109(-27,0) 110(-27.25,-8.2) 111(-27.5,0) 112(-27.75,-8.2) 113(-28,0) 114(-28.25,-8.2) 115(-28.5,0) 116(-28.75,-8.2) 117(-29,0) 118(-29.25,-8.2) 119(-29.5,0) 120(-29.75,-8.2) 121(-30,0) 122(-30.25,-8.2) 123(-30.5,0) 124(-30.75,-8.2) 125(-31,0) 126(-31.25,-8.2) 127(-31.5,0) 128(-31.75,-8.2) 129(-32,0) 130(-32.25,-8.2) 131(-32.5,0) 132(-32.75,-8.2) 133(-33,0) 134(-33.25,-8.2) 135(-33.5,0) 136(-33.75,-8.2) 137(-34,0) 138(-34.25,-8.2) 139(-34.5,0) 140(-34.75,-8.2) 141(-35,0) 142(-35.25,-8.2) 143(-35.5,0) 144(-35.75,-8.2) 145(-38,0) 146(-38.25,-8.2) 147(-38.5,0) 148(-38.75,-8.2) 149(-39,0) 150(-39.25,-8.2) 151(-39.5,0) 152(-39.75,-8.2) 153(-40,0) 154(-40.25,-8.2) 155(-40.5,0) 156(-40.75,-8.2) 157(-41,0) 158(-41.25,-8.2) 159(-41.5,0) 160(-41.75,-8.2) 161(-42,0) 162(-42.25,-8.2) 163(-42.5,0) 164(-42.75,-8.2) 165(-43,0) 166(-43.25,-8.2) 167(-43.5,0) 168(-43.75,-8.2) 169(-44,0) 170(-44.25,-8.2) 171(-44.5,0) 172(-44.75,-8.2) 173(-45,0) 174(-45.25,-8.2) 175(-45.5,0) 176(-45.75,-8.2) 177(-46,0) 178(-46.25,-8.2) 179(-46.5,0) 180(-46.75,-8.2) 181(-47,0) 182(-47.25,-8.2) 183(-47.5,0) 184(-47.75,-8.2) 185(-48,0) 186(-48.25,-8.2) 187(-48.5,0) 188(-48.75,-8.2) 189(-49,0) 190(-49.25,-8.2) 191(-49.5,0) 192(-49.75,-8.2) 193(-50,0) 194(-50.25,-8.2) 195(-50.5,0) 196(-50.75,-8.2) 197(-51,0) 198(-51.25,-8.2) 199(-51.5,0) 200(-51.75,-8.2) 201(-52,0) 202(-52.25,-8.2) 203(-52.5,0) 204(-52.75,-8.2) 205(-53,0) 206(-53.25,-8.2) 207(-53.5,0) 208(-53.75,-8.2) 209(-54,0) 210(-54.25,-8.2) 211(-54.5,0) 212(-54.75,-8.2) 213(-55,0) 214(-55.25,-8.2) 215(-55.5,0) 216(-55.75,-8.2) 217(-56,0) 218(-56.25,-8.2) 219(-56.5,0) 220(-56.75,-8.2) 221(-57,0) 222(-57.25,-8.2) 223(-57.5,0) 224(-57.75,-8.2) 225(-58,0) 226(-58.25,-8.2) 227(-58.5,0) 228(-58.75,-8.2) 229(-59,0) 230(-59.25,-8.2) 231(-59.5,0) 232(-59.75,-8.2) 233(-60,0) 234(-60.25,-8.2) 235(-60.5,0) 236(-60.75,-8.2) 237(-61,0) 238(-61.25,-8.2) 239(-61.5,0) 240(-61.75,-8.2) 241(-62,0) 242(-62.25,-8.2) 243(-62.5,0) 244(-62.75,-8.2) 245(-63,0) 246(-63.25,-8.2) 247(-63.5,0) 248(-63.75,-8.2) 249(-64,0) 250(-64.25,-8.2) 251(-64.5,0) 252(-64.75,-8.2) 253(-65,0) 254(-65.25,-8.2) 255(-65.5,0) 256(-65.75,-8.2) 257(-66,0) 258(-66.25,-8.2) 259(-66.5,0) 260(-66.75,-8.2)
  rect 3.505x4.597 smd: 261(0.425,-16.1) 262(-67.175,-16.1)
DEREN_40-42271-26001RHF_260P-T
  round 1.6 hole 1.6 unplated: (-1.025,4.1)
  round 1.092 hole 1.092 unplated: (67.775,4.1)
  oval 0.305x1.753 smd: 1(0,0) 2(0.25,8.2) 3(0.5,0) 4(0.75,8.2) 5(1,0) 6(1.25,8.2) 7(1.5,0) 8(1.75,8.2) 9(2,0) 10(2.25,8.2) 11(2.5,0) 12(2.75,8.2) 13(3,0) 14(3.25,8.2) 15(3.5,0) 16(3.75,8.2) 17(4,0) 18(4.25,8.2) 19(4.5,0) 20(4.75,8.2) 21(5,0) 22(5.25,8.2) 23(5.5,0) 24(5.75,8.2) 25(6,0) 26(6.25,8.2) 27(6.5,0) 28(6.75,8.2) 29(7,0) 30(7.25,8.2) 31(7.5,0) 32(7.75,8.2) 33(8,0) 34(8.25,8.2) 35(8.5,0) 36(8.75,8.2) 37(9,0) 38(9.25,8.2) 39(9.5,0) 40(9.75,8.2) 41(10,0) 42(10.25,8.2) 43(10.5,0) 44(10.75,8.2) 45(11,0) 46(11.25,8.2) 47(11.5,0) 48(11.75,8.2) 49(12,0) 50(12.25,8.2) 51(12.5,0) 52(12.75,8.2) 53(13,0) 54(13.25,8.2) 55(13.5,0) 56(13.75,8.2) 57(14,0) 58(14.25,8.2) 59(14.5,0) 60(14.75,8.2) 61(15,0) 62(15.25,8.2) 63(15.5,0) 64(15.75,8.2) 65(16,0) 66(16.25,8.2) 67(16.5,0) 68(16.75,8.2) 69(17,0) 70(17.25,8.2) 71(17.5,0) 72(17.75,8.2) 73(18,0) 74(18.25,8.2) 75(18.5,0) 76(18.75,8.2) 77(19,0) 78(19.25,8.2) 79(19.5,0) 80(19.75,8.2) 81(20,0) 82(20.25,8.2) 83(20.5,0) 84(20.75,8.2) 85(21,0) 86(21.25,8.2) 87(21.5,0) 88(21.75,8.2) 89(22,0) 90(22.25,8.2) 91(22.5,0) 92(22.75,8.2) 93(23,0) 94(23.25,8.2) 95(23.5,0) 96(23.75,8.2) 97(24,0) 98(24.25,8.2) 99(24.5,0) 100(24.75,8.2) 101(25,0) 102(25.25,8.2) 103(25.5,0) 104(25.75,8.2) 105(26,0) 106(26.25,8.2) 107(26.5,0) 108(26.75,8.2) 109(27,0) 110(27.25,8.2) 111(27.5,0) 112(27.75,8.2) 113(28,0) 114(28.25,8.2) 115(28.5,0) 116(28.75,8.2) 117(29,0) 118(29.25,8.2) 119(29.5,0) 120(29.75,8.2) 121(30,0) 122(30.25,8.2) 123(30.5,0) 124(30.75,8.2) 125(31,0) 126(31.25,8.2) 127(31.5,0) 128(31.75,8.2) 129(32,0) 130(32.25,8.2) 131(32.5,0) 132(32.75,8.2) 133(33,0) 134(33.25,8.2) 135(33.5,0) 136(33.75,8.2) 137(34,0) 138(34.25,8.2) 139(34.5,0) 140(34.75,8.2) 141(35,0) 142(35.25,8.2) 143(35.5,0) 144(35.75,8.2) 145(38,0) 146(38.25,8.2) 147(38.5,0) 148(38.75,8.2) 149(39,0) 150(39.25,8.2) 151(39.5,0) 152(39.75,8.2) 153(40,0) 154(40.25,8.2) 155(40.5,0) 156(40.75,8.2) 157(41,0) 158(41.25,8.2) 159(41.5,0) 160(41.75,8.2) 161(42,0) 162(42.25,8.2) 163(42.5,0) 164(42.75,8.2) 165(43,0) 166(43.25,8.2) 167(43.5,0) 168(43.75,8.2) 169(44,0) 170(44.25,8.2) 171(44.5,0) 172(44.75,8.2) 173(45,0) 174(45.25,8.2) 175(45.5,0) 176(45.75,8.2) 177(46,0) 178(46.25,8.2) 179(46.5,0) 180(46.75,8.2) 181(47,0) 182(47.25,8.2) 183(47.5,0) 184(47.75,8.2) 185(48,0) 186(48.25,8.2) 187(48.5,0) 188(48.75,8.2) 189(49,0) 190(49.25,8.2) 191(49.5,0) 192(49.75,8.2) 193(50,0) 194(50.25,8.2) 195(50.5,0) 196(50.75,8.2) 197(51,0) 198(51.25,8.2) 199(51.5,0) 200(51.75,8.2) 201(52,0) 202(52.25,8.2) 203(52.5,0) 204(52.75,8.2) 205(53,0) 206(53.25,8.2) 207(53.5,0) 208(53.75,8.2) 209(54,0) 210(54.25,8.2) 211(54.5,0) 212(54.75,8.2) 213(55,0) 214(55.25,8.2) 215(55.5,0) 216(55.75,8.2) 217(56,0) 218(56.25,8.2) 219(56.5,0) 220(56.75,8.2) 221(57,0) 222(57.25,8.2) 223(57.5,0) 224(57.75,8.2) 225(58,0) 226(58.25,8.2) 227(58.5,0) 228(58.75,8.2) 229(59,0) 230(59.25,8.2) 231(59.5,0) 232(59.75,8.2) 233(60,0) 234(60.25,8.2) 235(60.5,0) 236(60.75,8.2) 237(61,0) 238(61.25,8.2) 239(61.5,0) 240(61.75,8.2) 241(62,0) 242(62.25,8.2) 243(62.5,0) 244(62.75,8.2) 245(63,0) 246(63.25,8.2) 247(63.5,0) 248(63.75,8.2) 249(64,0) 250(64.25,8.2) 251(64.5,0) 252(64.75,8.2) 253(65,0) 254(65.25,8.2) 255(65.5,0) 256(65.75,8.2) 257(66,0) 258(66.25,8.2) 259(66.5,0) 260(66.75,8.2)
  rect 3.505x4.597 smd: 261(-0.425,-7.9) 262(67.175,-7.9)
DMN66D0LDW-7_SOT363-6
  oval 0.432x0.61 smd: 1(0,0) 2(0.65,0) 3(1.3,0) 4(1.3,1.9) 5(0.65,1.9) 6(0,1.9)
EM5209VF_DFN14_3X2-S
  oval 0.203x0.711 smd: 1(0,0) 2(0.4,0) 3(0.8,0) 4(1.2,0) 5(1.6,0) 6(2,0) 7(2.4,0) 8(2.4,2) 9(2,2) 10(1.6,2) 11(1.2,2) 12(0.8,2) 13(0.4,2) 14(0,2)
  rect 2.591x0.991 smd: 15(1.2,1)
F_1206L150PR
  rect 0.991x1.803 smd: 1(0,0) 2(2.8,0)
F_MF-NSMF050-2
  rect 0.991x1.6 smd: 1(0,0) 2(3,0)
F_SMD1812P110TF-24
  rect 1.778x3.15 smd: 1(0,0) 2(5.23,0)
FDV301N_NL_SOT23-3
  oval 1.016x1.524 smd: 1(0,0) 2(0.965,2.083) 3(-0.965,2.083)
FIDUCIAL_C40M80
  round 1.016 smd: 1(0,0)
H_3P0-G
  round 3.505 hole 2.997: 1(0,0)
H_3P0N
  round 2.997 hole 2.997 unplated: (0,0)
H_3P2
  round 3.708 hole 3.2: 1(0,0)
H_3P2X2P6
  oval 3.708x3.099 hole 3.2x2.591: 1(0,0)
H_3P7
  round 4.216 hole 3.708: 1(0,0)
H_3P7X4P3
  oval 4.216x4.801 hole 3.708x4.293: 1(0,0)
H_3P9
  round 4.42 hole 3.912: 1(0,0)
H_5P6N
  round 5.588 hole 5.588 unplated: (0,0)
INPAQ_HCM1012GH900BP_4P-NPM
  rect 0.711x0.305 smd: 1(0,0) 2(1.25,0) 3(1.25,-0.5) 4(0,-0.5)
INPAQ_MCM1012B900F06BP_4P
  rect 0.711x0.305 smd: 1(0,0) 2(1.25,0) 3(1.25,-0.5) 4(0,-0.5)
INPAQ_MCM1012B900F06BP_4P-NPM
  rect 0.711x0.305 smd: 1(0,0) 2(1.25,0) 3(1.25,-0.5) 4(0,-0.5)
IP4292CZ10-TBR_XSON10_2P5X1
  oval 0.254x0.889 smd: 1(0,0)
  oval 0.254x0.838 smd: 2(0.5,-0.025) 3(1,-0.025) 4(1.5,-0.025) 5(2,-0.025) 6(2,1.125) 7(1.5,1.125) 8(1,1.125) 9(0.5,1.125) 10(0,1.125)
ISL62883CHRTZ-T_TQFN40_5X5-S
  oval 0.203x0.991 smd: 1(0,0) 2(0.4,0) 3(0.8,0) 4(1.2,0) 5(1.6,0) 6(2,0) 7(2.4,0) 8(2.8,0) 9(3.2,0) 10(3.6,0) 21(3.6,4.95) 22(3.2,4.95) 23(2.8,4.95) 24(2.4,4.95) 25(2,4.95) 26(1.6,4.95) 27(1.2,4.95) 28(0.8,4.95) 29(0.4,4.95) 30(0,4.95)
  oval 0.991x0.203 smd: 11(4.275,0.675) 12(4.275,1.075) 13(4.275,1.475) 14(4.275,1.875) 15(4.275,2.275) 16(4.275,2.675) 17(4.275,3.075) 18(4.275,3.475) 19(4.275,3.875) 20(4.275,4.275) 31(-0.675,4.275) 32(-0.675,3.875) 33(-0.675,3.475) 34(-0.675,3.075) 35(-0.675,2.675) 36(-0.675,2.275) 37(-0.675,1.875) 38(-0.675,1.475) 39(-0.675,1.075) 40(-0.675,0.675)
  rect 3.505x3.505 smd: 41(1.8,2.475)
ISL95520HRZ-T_QFN32_4X4-S
  oval 0.889x0.203 smd: 1(0,0) 2(0,-0.4) 3(0,-0.8) 4(0,-1.2) 5(0,-1.6) 6(0,-2) 7(0,-2.4) 8(0,-2.8) 17(4.1,-2.8) 18(4.1,-2.4) 19(4.1,-2) 20(4.1,-1.6) 21(4.1,-1.2) 22(4.1,-0.8) 23(4.1,-0.4) 24(4.1,0)
  oval 0.203x0.889 smd: 9(0.65,-3.45) 10(1.05,-3.45) 11(1.45,-3.45) 12(1.85,-3.45) 13(2.25,-3.45) 14(2.65,-3.45) 15(3.05,-3.45) 16(3.45,-3.45) 25(3.45,0.65) 26(3.05,0.65) 27(2.65,0.65) 28(2.25,0.65) 29(1.85,0.65) 30(1.45,0.65) 31(1.05,0.65) 32(0.65,0.65)
  rect 2.642x2.642 smd: 33(2.05,-1.4)
ISL95808HRZ-TS2378_DFN8_2X2-S
  oval 0.254x0.787 smd: 1(0,0) 2(0.5,0) 3(1,0) 4(1.5,0) 5(1.5,2.2) 6(1,2.2) 7(0.5,2.2) 8(0,2.2)
  rect 1.549x0.889 smd: 9(0.75,1.1)
JUMP_43X39
  custom 0.191x0.191 smd: 1(0,0) 2(0.914,0)
JUMP_43X79
  custom 0.188x0.188 smd: 1(0,0) 2(1.1,0)
JUMP_43X79-NPM
  custom 0.188x0.188 smd: 1(0,0) 2(1.1,0)
JUMP_43X118
  custom 0.187x0.187 smd: 1(0,0) 2(1.1,0)
JUMP_43X118-NPM
  custom 0.187x0.187 smd: 1(0,0) 2(1.1,0)
JXT_FP202DH-008M10M_8P
  oval 0.61x1.448 smd: 1(0,0) 2(1,0) 3(2,0) 4(3,0) 5(4,0) 6(5,0) 7(6,0) 8(7,0)
  rect 2.159x2.21 smd: 9(-2.825,-3.125) 10(9.825,-3.125)
JXT_FP226H-006S1BM_6P
  oval 0.61x1.295 smd: 1(0,0) 2(1,0) 3(2,0) 4(3,0) 5(4,0) 6(5,0)
  rect 0.991x2.007 smd: 7(-2.6,-3.25) 8(7.6,-3.25)
JXT_FP241AH-010GAAM_10P
  oval 0.305x1.092 smd: 1(0,0) 2(0.5,0) 3(1,0) 4(1.5,0) 5(2,0) 6(2.5,0) 7(3,0) 8(3.5,0) 9(4,0) 10(4.5,0)
  rect 0.406x0.787 smd: 11(-1,-2.65) 12(5.5,-2.65)
JXT_WB247H-004S10M_4P
  oval 0.61x1.549 smd: 1(0,0) 2(1,0) 3(2,0) 4(3,0)
  rect 1.194x1.803 smd: 5(-1.3,-3.875) 6(4.3,-3.875)
L2N7002WT1G_SC70-3
  oval 0.711x0.889 smd: 1(0,0) 2(0.65,1.9) 3(-0.65,1.9)
L03ESDL5V0CC3-2_SOT23-3
  oval 1.016x1.524 smd: 1(0,0) 2(0.965,2.083) 3(-0.965,2.083)
L05ESDL5V0NA-4_SLP2510P8-10-9
  rect 0.203x0.686 smd: 1(0,0) 2(-0.5,0) 4(-1.5,0) 5(-2,0) 6(-2,-0.875) 7(-1.5,-0.875) 8(-0.5,-0.875) 9(0,-0.875)
  rect 0.406x1.549 smd: 3(-1,-0.437)
L_5X5X3_M
  custom 0.54x0.54 smd: 1(0,0) 4(4.35,0)
  rect 0.762x0.508 smd: 2(0.699,0) 3(3.652,0)
L_5X5X3_M_2P
  rect 2.159x2.794 smd: 1(0,0) 2(4.35,0)
L_5X5X3_M_2P-NPM
  rect 2.159x2.794 smd: 1(0,0) 2(4.35,0)
L_7X7X3_M_2P
  rect 2.362x3.505 smd: 1(0,0) 2(6.05,0)
L_7X7X4_M
  custom 0.591x0.591 smd: 1(0,0) 4(6.05,0)
  rect 0.762x0.508 smd: 2(0.8,0) 3(5.25,0)
LCN_DAN05-67406-0100_67P
  round 1.092 hole 1.092 unplated: (-0.75,-5.275)
  round 1.6 hole 1.6 unplated: (19.25,-5.275)
  oval 0.305x1.549 smd: 1(0,0) 2(0.25,-7.55) 3(0.5,0) 4(0.75,-7.55) 5(1,0) 6(1.25,-7.55) 7(1.5,0) 8(3.75,-7.55) 9(4,0) 10(4.25,-7.55) 11(4.5,0) 12(4.75,-7.55) 13(5,0) 14(5.25,-7.55) 15(5.5,0) 16(5.75,-7.55) 17(6,0) 18(6.25,-7.55) 19(6.5,0) 20(6.75,-7.55) 21(7,0) 22(7.25,-7.55) 23(7.5,0) 24(7.75,-7.55) 25(8,0) 26(8.25,-7.55) 27(8.5,0) 28(8.75,-7.55) 29(9,0) 30(9.25,-7.55) 31(9.5,0) 32(9.75,-7.55) 33(10,0) 34(10.25,-7.55) 35(10.5,0) 36(10.75,-7.55) 37(11,0) 38(11.25,-7.55) 39(11.5,0) 40(11.75,-7.55) 41(12,0) 42(12.25,-7.55) 43(12.5,0) 44(12.75,-7.55) 45(13,0) 46(13.25,-7.55) 47(13.5,0) 48(13.75,-7.55) 49(14,0) 50(14.25,-7.55) 51(14.5,0) 52(14.75,-7.55) 53(15,0) 54(15.25,-7.55) 55(15.5,0) 56(15.75,-7.55) 57(16,0) 58(16.25,-7.55) 59(16.5,0) 60(16.75,-7.55) 61(17,0) 62(17.25,-7.55) 63(17.5,0) 64(17.75,-7.55) 65(18,0) 66(18.25,-7.55) 67(18.5,0)
  rect 1.194x2.743 smd: 68(-1.1,-0.775) 69(19.6,-0.775)
LMBT3904LT1G_SOT23-3
  oval 1.016x1.524 smd: 1(0,0) 2(0.965,2.083) 3(-0.965,2.083)
LMUN5113T1G_SOT323-3
  oval 0.711x0.889 smd: 1(0,0) 2(0.65,1.9) 3(-0.65,1.9)
LN2306LT1G_SOT23-3
  oval 1.016x1.524 smd: 1(0,0) 2(0.965,2.083) 3(-0.965,2.083)
LRB715FT1G_SOT323-3
  oval 0.711x0.889 smd: 1(0,0) 2(0.65,1.9) 3(-0.65,1.9)
LTC015EUBFS8TL_UMT3F
  oval 0.787x0.889 smd: 1(0,0) 2(-0.65,-1.6) 3(0.65,-1.6)
MDU1512RH_POWERDFN56-8-5
  oval 0.61x1.27 smd: 1(0,0) 2(1.27,0) 3(2.54,0) 4(3.81,0)
  custom 1.105x1.105 smd: 5(1.905,3.715)
MEC1404-NU-TR_VTQFP128_14X14
  oval 1.753x0.203 smd: 1(0,0) 2(0,-0.4) 3(0,-0.8) 4(0,-1.2) 5(0,-1.6) 6(0,-2) 7(0,-2.4) 8(0,-2.8) 9(0,-3.2) 10(0,-3.6) 11(0,-4) 12(0,-4.4) 13(0,-4.8) 14(0,-5.2) 15(0,-5.6) 16(0,-6) 17(0,-6.4) 18(0,-6.8) 19(0,-7.2) 20(0,-7.6) 21(0,-8) 22(0,-8.4) 23(0,-8.8) 24(0,-9.2) 25(0,-9.6) 26(0,-10) 27(0,-10.4) 28(0,-10.8) 29(0,-11.2) 30(0,-11.6) 31(0,-12) 32(0,-12.4) 65(15.654,-12.4) 66(15.654,-12) 67(15.654,-11.6) 68(15.654,-11.2) 69(15.654,-10.8) 70(15.654,-10.4) 71(15.654,-10) 72(15.654,-9.6) 73(15.654,-9.2) 74(15.654,-8.8) 75(15.654,-8.4) 76(15.654,-8) 77(15.654,-7.6) 78(15.654,-7.2) 79(15.654,-6.8) 80(15.654,-6.4) 81(15.654,-6) 82(15.654,-5.6) 83(15.654,-5.2) 84(15.654,-4.8) 85(15.654,-4.4) 86(15.654,-4) 87(15.654,-3.6) 88(15.654,-3.2) 89(15.654,-2.8) 90(15.654,-2.4) 91(15.654,-2) 92(15.654,-1.6) 93(15.654,-1.2) 94(15.654,-0.8) 95(15.654,-0.4) 96(15.654,0)
  oval 0.203x1.753 smd: 33(1.627,-14.027) 34(2.027,-14.027) 35(2.427,-14.027) 36(2.827,-14.027) 37(3.227,-14.027) 38(3.627,-14.027) 39(4.027,-14.027) 40(4.427,-14.027) 41(4.827,-14.027) 42(5.227,-14.027) 43(5.627,-14.027) 44(6.027,-14.027) 45(6.427,-14.027) 46(6.827,-14.027) 47(7.227,-14.027) 48(7.627,-14.027) 49(8.027,-14.027) 50(8.427,-14.027) 51(8.827,-14.027) 52(9.227,-14.027) 53(9.627,-14.027) 54(10.027,-14.027) 55(10.427,-14.027) 56(10.827,-14.027) 57(11.227,-14.027) 58(11.627,-14.027) 59(12.027,-14.027) 60(12.427,-14.027) 61(12.827,-14.027) 62(13.227,-14.027) 63(13.627,-14.027) 64(14.027,-14.027) 97(14.027,1.627) 98(13.627,1.627) 99(13.227,1.627) 100(12.827,1.627) 101(12.427,1.627) 102(12.027,1.627) 103(11.627,1.627) 104(11.227,1.627) 105(10.827,1.627) 106(10.427,1.627) 107(10.027,1.627) 108(9.627,1.627) 109(9.227,1.627) 110(8.827,1.627) 111(8.427,1.627) 112(8.027,1.627) 113(7.627,1.627) 114(7.227,1.627) 115(6.827,1.627) 116(6.427,1.627) 117(6.027,1.627) 118(5.627,1.627) 119(5.227,1.627) 120(4.827,1.627) 121(4.427,1.627) 122(4.027,1.627) 123(3.627,1.627) 124(3.227,1.627) 125(2.827,1.627) 126(2.427,1.627) 127(2.027,1.627) 128(1.627,1.627)
MHPC_NS681677_12P
  oval 0.635x1.905 smd: 1(0,0) 2(1.27,0) 3(2.54,0) 4(6.35,0) 5(7.62,0) 6(8.89,0) 7(8.89,8.765) 8(7.62,8.765) 9(6.35,8.765) 10(2.54,8.765) 11(1.27,8.765) 12(0,8.765)
MURAT_BLM15AG102SN1D_2P
  rect 0.457x0.508 smd: 1(0,0) 2(0.85,0)
MURAT_BLM15BD601SN1D_2P
  rect 0.508x0.762 smd: 1(0,0) 2(0.75,0)
MURAT_BLM15PD600SN1D_2P
  rect 0.508x0.762 smd: 1(0,0) 2(0.75,0)
MURAT_BLM15PX221SN1D_2P
  rect 0.457x0.508 smd: 1(0,0) 2(0.85,0)
MURAT_BLM15PX330SN1D_2P
  rect 0.508x0.762 smd: 1(0,0) 2(0.75,0)
NB681GD-Z_QFN13_2X3
  oval 1.702x0.254 smd: 1(0,0) 2(0,-1) 8(1.3,-0.5)
  oval 0.254x0.889 smd: 3(-0.1,-2.05) 4(0.4,-2.05) 5(0.9,-2.05) 6(1.4,-2.05) 10(1.4,1.05) 11(0.9,1.05) 12(0.4,1.05) 13(-0.1,1.05)
  oval 0.889x0.254 smd: 7(1.706,-1) 9(1.706,0)
NCT7718W_MSOP8
  oval 0.381x1.575 smd: 1(0,0) 2(0.65,0) 3(1.3,0) 4(1.95,0) 5(1.95,4.35) 6(1.3,4.35) 7(0.65,4.35) 8(0,4.35)
PESD5V0U2BT_SOT23-3
  oval 1.016x1.524 smd: 1(0,0) 2(0.965,2.083) 3(-0.965,2.083)
R0402_0OHM
  rect 0.508x0.559 smd: 1(0,0) 2(0.914,0)
R0603_0OHM
  rect 0.635x0.889 smd: 1(0,0) 2(1.397,0)
R0805_0OHM
  rect 0.813x1.397 smd: 1(0,0) 2(1.702,0)
R_0402
  rect 0.508x0.559 smd: 1(0,0) 2(0.914,0)
R_0402-NPM
  rect 0.508x0.559 smd: 1(0,0) 2(0.914,0)
R_0603
  rect 0.635x0.889 smd: 1(0,0) 2(1.397,0)
R_0805
  rect 0.813x1.397 smd: 1(0,0) 2(1.702,0)
R_1206
  rect 1.016x1.651 smd: 1(0,0) 2(2.667,0)
R_1206_4P
  custom 0.476x0.476 smd: 1(0,0) 4(5.08,0)
  rect 1.397x0.381 smd: 2(1.206,0) 3(3.873,0)
RB551V-30_SOD323-2
  rect 0.559x0.813 smd: 1(0,0) 2(2.3,0)
RB751S40T1G_SOD523-2
  rect 0.406x0.406 smd: 1(0,0) 2(1.4,0)
RHU002N06_SOT323-3
  oval 0.813x0.914 smd: 1(0,0) 2(0.65,1.6) 3(-0.65,1.6)
RP_0804_8P4R
  oval 0.66x0.254 smd: 1(0,0) 2(0,-0.5) 3(0,-1) 4(0,-1.5) 5(1.15,-1.5) 6(1.15,-1) 7(1.15,-0.5) 8(1.15,0)
RT8207PGQW_WQFN20_3X3-S
  oval 0.203x0.889 smd: 1(0,0) 2(0.4,0) 3(0.8,0) 4(1.2,0) 5(1.6,0) 11(1.6,3.1) 12(1.2,3.1) 13(0.8,3.1) 14(0.4,3.1) 15(0,3.1)
  oval 0.889x0.203 smd: 6(2.35,0.75) 7(2.35,1.15) 8(2.35,1.55) 9(2.35,1.95) 10(2.35,2.35) 16(-0.75,2.35) 17(-0.75,1.95) 18(-0.75,1.55) 19(-0.75,1.15) 20(-0.75,0.75)
  rect 1.702x1.702 smd: 21(0.8,1.55)
RT904225GSP_SO8
  oval 0.635x1.854 smd: 1(0,0) 2(1.27,0) 3(2.54,0) 4(3.81,0) 5(3.81,5.157) 6(2.54,5.157) 7(1.27,5.157) 8(0,5.157)
  rect 2.159x2.159 smd: 9(1.905,2.579)
RTL8106E-CG_QFN32_4X4-S
  oval 0.203x0.838 smd: 1(0,0) 2(0.4,0) 3(0.8,0) 4(1.2,0) 5(1.6,0) 6(2,0) 7(2.4,0) 8(2.8,0) 17(2.8,4.15) 18(2.4,4.15) 19(2,4.15) 20(1.6,4.15) 21(1.2,4.15) 22(0.8,4.15) 23(0.4,4.15) 24(0,4.15)
  oval 0.838x0.203 smd: 9(3.475,0.675) 10(3.475,1.075) 11(3.475,1.475) 12(3.475,1.875) 13(3.475,2.275) 14(3.475,2.675) 15(3.475,3.075) 16(3.475,3.475) 25(-0.675,3.475) 26(-0.675,3.075) 27(-0.675,2.675) 28(-0.675,2.275) 29(-0.675,1.875) 30(-0.675,1.475) 31(-0.675,1.075) 32(-0.675,0.675)
  rect 2.692x2.692 smd: 33(1.4,2.075)
RUM002N02GT2L_VMT3
  oval 0.508x0.457 smd: 1(0,0)
  oval 0.406x0.457 smd: 2(-0.4,-1.15) 3(0.4,-1.15)
SANTA_130460-N_8P-T
  round 1.295 hole 0.889: 1(0,0) 2(-1.02,1.1) 3(-2.04,0) 4(-3.06,1.1) 5(-4.08,0) 6(-5.1,1.1) 7(-6.12,0) 8(-7.14,1.1)
  oval 0.991x2.007 hole 0.61x1.6: 9(4.83,-10.1) 10(4.83,-2.3) 11(-11.97,-2.3) 12(-11.97,-10.1)
SDMK0340L-7-F_SOD323-2
  rect 1.346x0.66 smd: 1(0,0) 2(2.4,0)
SHORTPADS
  custom 0.19x0.19 smd: 1(-0.483,0) 2(0.483,0)
SIS412DN-T1-GE3_POWERPAK8-5
  oval 0.406x0.991 smd: 1(0,0) 2(0.66,0) 3(1.32,0) 4(1.98,0)
  custom 0.559x0.559 smd: 5(0.99,2.247)
SKL-U_BGA_1356P-T
  round 0.356 smd: A3(-0.965,0) A70(-40.166,0) B2(-0.483,0.483) B71(-40.629,0.462) BA1(0,22.166) BA71(-40.629,22.166) BB2(-0.462,22.628) BB70(-40.166,22.628) C1(0,0.965)
  round 0.33 smd: A4(-1.615,0) A69(-39.516,0) AY1(0,21.516) AY71(-40.629,21.516) B3(-1.118,0.635) B70(-39.999,0.63) BA2(-0.629,21.999) BA70(-39.999,21.999) BB3(-1.113,22.628) BB69(-39.516,22.628) C2(-0.635,1.118) C71(-40.629,1.113) D1(0,1.615)
  round 0.305 smd: A5(-2.266,0) A68(-38.866,0) AA2(-0.975,10.804) AA4(-1.951,10.804) AA63(-35.427,10.719) AA64(-36.077,10.719) AA65(-36.727,10.719) AA66(-37.377,10.719) AA67(-38.028,10.719) AA68(-38.678,10.719) AA69(-39.328,10.719) AA70(-39.978,10.719) AA71(-40.629,10.719) AB4(-1.951,11.467) AB6(-2.729,11.181) AB7(-3.379,11.181) AB8(-4.029,11.181) AB9(-4.679,11.181) AB10(-5.33,11.181) AB11(-5.98,11.181) AB12(-6.63,11.181) AB13(-7.28,11.181) AB15(-8.126,11.305) AB16(-8.776,11.305) AB17(-9.426,11.305) AB18(-10.077,11.305) AB19(-10.727,11.305) AB20(-11.377,11.305) AB21(-12.027,11.305) AB62(-34.958,11.176) AC3(-1.626,12.13) AC63(-35.427,11.633) AC64(-36.077,11.633) AC65(-36.727,11.633) AC66(-37.377,11.633) AC67(-38.028,11.633) AC68(-38.678,11.633) AC69(-39.328,11.633) AC70(-39.978,11.633) AC71(-40.629,11.633) AD4(-1.951,12.792) AD6(-2.729,12.248) AD7(-3.379,12.248) AD8(-4.029,12.248) AD9(-4.679,12.248) AD10(-5.33,12.248) AD11(-5.98,12.248) AD12(-6.63,12.248) AD13(-7.28,12.248) AD15(-8.126,12.143) AD16(-8.776,12.143) AD17(-9.426,12.143) AD18(-10.077,12.143) AD19(-10.727,12.143) AD20(-11.377,12.143) AD21(-12.027,12.143) AD62(-34.958,12.09) AE62(-34.958,13.005) AE63(-35.427,12.547) AE64(-36.077,12.547) AE65(-36.727,12.547) AE66(-37.377,12.547) AE67(-38.028,12.547) AE68(-38.678,12.547) AE69(-39.328,12.547) AF2(-0.975,13.455) AF4(-1.951,13.455) AF6(-2.729,13.315) AF7(-3.379,13.315) AF8(-4.029,13.315) AF9(-4.679,13.315) AF10(-5.33,13.315) AF11(-5.98,13.315) AF12(-6.63,13.315) AF13(-7.28,13.315) AF15(-8.126,12.982) AF16(-8.776,12.982) AF17(-9.426,12.982) AF18(-10.077,12.982) AF19(-10.727,12.982) AF20(-11.377,12.982) AF21(-12.027,12.982) AF63(-35.427,13.462) AF64(-36.077,13.462) AF65(-36.727,13.462) AF66(-37.377,13.462) AF67(-38.028,13.462) AF68(-38.678,13.253) AF69(-39.328,13.253) AG4(-1.951,14.118) AG15(-8.126,13.82) AG16(-8.776,13.82) AG17(-9.426,13.82) AG18(-10.077,13.82) AG19(-10.727,13.82) AG20(-11.377,13.82) AG21(-12.027,13.82) AG62(-34.958,13.919) AG69(-39.003,13.916) AH3(-1.626,14.781) AH6(-2.729,14.381) AH7(-3.379,14.381) AH8(-4.029,14.381) AH9(-4.679,14.381) AH10(-5.33,14.381) AH11(-5.98,14.381) AH12(-6.63,14.381) AH13(-7.28,14.381) AH63(-35.427,14.376) AH64(-36.077,14.376) AH65(-36.727,14.376) AH66(-37.377,14.376) AH67(-38.028,14.376) AJ4(-1.951,15.444) AJ15(-8.126,14.658) AJ16(-8.776,14.658) AJ17(-9.426,14.658) AJ18(-10.077,14.658) AJ19(-10.727,14.658) AJ20(-11.377,14.658) AJ21(-12.027,14.658) AJ62(-34.958,14.833) AK6(-2.729,15.321) AK7(-3.379,15.321) AK8(-4.029,15.321) AK9(-4.679,15.321) AK10(-5.33,15.321) AK11(-5.98,15.321) AK12(-6.63,15.321) AK13(-7.28,15.321) AK15(-8.126,15.496) AK16(-8.776,15.496) AK17(-9.426,15.496) AK18(-10.077,15.496) AK19(-10.727,15.496) AK20(-11.377,15.496) AK21(-12.027,15.496) AK22(-12.719,15.323) AK23(-13.633,15.323) AK25(-14.547,15.323) AK27(-15.462,15.323) AK28(-16.376,15.323) AK30(-17.291,15.323) AK32(-18.205,15.323) AK33(-19.119,15.323) AK35(-20.034,15.323) AK37(-20.948,15.323) AK38(-21.863,15.323) AK40(-22.777,15.323) AK42(-23.691,15.323) AK43(-24.606,15.323) AK45(-25.52,15.323) AK46(-26.435,15.323) AK48(-27.349,15.323) AK50(-28.263,15.323) AK52(-29.178,15.323) AK53(-30.092,15.323) AK55(-31.007,15.323) AK56(-31.921,15.323) AK58(-32.835,15.323) AK60(-33.75,15.323) AK62(-34.774,15.458) AK63(-35.427,15.291) AK64(-36.077,15.291) AK65(-36.727,15.291) AK66(-37.377,15.291) AK67(-38.028,15.291) AK68(-38.678,15.143) AK69(-39.653,15.143) AL2(-0.975,16.107) AL4(-1.951,16.107) AL23(-13.176,15.788) AL25(-14.09,15.788) AL27(-15.005,15.788) AL28(-15.919,15.788) AL30(-16.833,15.788) AL32(-17.748,15.788) AL33(-18.662,15.788) AL35(-19.577,15.788) AL37(-20.491,15.788) AL38(-21.405,15.788) AL40(-22.32,15.788) AL42(-23.234,15.788) AL43(-24.149,15.788) AL45(-25.063,15.788) AL46(-25.977,15.788) AL48(-26.892,15.788) AL50(-27.806,15.788) AL52(-28.721,15.788) AL53(-29.635,15.788) AL55(-30.549,15.788) AL56(-31.464,15.788) AL58(-32.378,15.788) AL60(-33.293,15.788) AL61(-34.207,15.788) AL63(-35.427,16.159) AL64(-36.077,16.159) AL65(-36.727,16.159) AL66(-37.377,16.159) AM4(-1.951,16.77) AM5(-2.66,16.261) AM7(-3.575,16.261) AM8(-4.489,16.261) AM10(-5.403,16.261) AM11(-6.318,16.261) AM13(-7.232,16.261) AM15(-8.147,16.261) AM16(-9.061,16.261) AM18(-9.975,16.261) AM20(-10.89,16.261) AM21(-11.804,16.261) AM22(-12.719,16.261) AM23(-13.633,16.261) AM25(-14.547,16.261) AM27(-15.462,16.261) AM28(-16.376,16.261) AM30(-17.291,16.261) AM32(-18.205,16.261) AM33(-19.119,16.261) AM35(-20.034,16.261) AM37(-20.948,16.261) AM38(-21.863,16.261) AM40(-22.777,16.261) AM42(-23.691,16.261) AM43(-24.606,16.261) AM45(-25.52,16.261) AM46(-26.435,16.261) AM48(-27.349,16.261) AM50(-28.263,16.261) AM52(-29.178,16.261) AM53(-30.092,16.261) AM55(-31.007,16.261) AM56(-31.921,16.261) AM58(-32.835,16.261) AM60(-33.75,16.261) AM61(-34.664,16.261) AM68(-38.353,16.37) AM69(-39.003,16.37) AN3(-1.626,17.433) AN5(-2.66,16.911) AN7(-3.575,16.911) AN8(-4.489,16.911) AN10(-5.403,16.911) AN11(-6.318,16.911) AN13(-7.232,16.911) AN15(-8.147,16.911) AN16(-9.061,16.911) AN18(-9.975,16.911) AN20(-10.89,16.911) AN21(-11.804,16.911) AN22(-12.719,16.911) AN23(-13.633,16.911) AN25(-14.547,16.911) AN27(-15.462,16.911) AN28(-16.376,16.911) AN30(-17.291,16.911) AN32(-18.205,16.911) AN33(-19.119,16.911) AN35(-20.034,16.911) AN37(-20.948,16.911) AN38(-21.863,16.911) AN40(-22.777,16.911) AN42(-23.691,16.911) AN43(-24.606,16.911) AN45(-25.52,16.911) AN46(-26.435,16.911) AN48(-27.349,16.911) AN50(-28.263,16.911) AN52(-29.178,16.911) AN53(-30.092,16.911) AN55(-31.007,16.911) AN56(-31.921,16.911) AN58(-32.835,16.911) AN60(-33.75,16.911) AN61(-34.664,16.911) AN63(-35.579,16.911) AN65(-36.493,16.911) AN66(-37.407,16.911) AN68(-38.678,17.033) AN69(-39.328,17.033) AP4(-1.951,18.096) AP5(-2.66,17.561) AP7(-3.575,17.561) AP8(-4.489,17.561) AP10(-5.403,17.561) AP11(-6.318,17.561) AP13(-7.232,17.561) AP15(-8.147,17.561) AP16(-9.061,17.561) AP18(-9.975,17.561) AP20(-10.89,17.561) AP21(-11.804,17.561) AP22(-12.719,17.561) AP23(-13.633,17.561) AP25(-14.547,17.561) AP27(-15.462,17.561) AP28(-16.376,17.561) AP30(-17.291,17.561) AP32(-18.205,17.561) AP33(-19.119,17.561) AP35(-20.034,17.561) AP37(-20.948,17.561) AP38(-21.863,17.561) AP40(-22.777,17.561) AP42(-23.691,17.561) AP43(-24.606,17.561) AP45(-25.52,17.561) AP46(-26.435,17.561) AP48(-27.349,17.561) AP50(-28.263,17.561) AP52(-29.178,17.561) AP53(-30.092,17.561) AP55(-31.007,17.561) AP56(-31.921,17.561) AP58(-32.835,17.561) AP60(-33.75,17.561) AP61(-34.664,17.561) AP63(-35.579,17.561) AP65(-36.493,17.561) AP66(-37.407,17.561) AP68(-38.353,17.646) AP70(-39.572,17.646) AR5(-2.66,18.211) AR7(-3.575,18.211) AR8(-4.489,18.211) AR10(-5.403,18.211) AR11(-6.318,18.211) AR13(-7.232,18.211) AR15(-8.147,18.211) AR16(-9.061,18.211) AR18(-9.975,18.211) AR20(-10.89,18.211) AR21(-11.804,18.211) AR22(-12.719,18.211) AR23(-13.633,18.211) AR25(-14.547,18.211) AR27(-15.462,18.211) AR28(-16.376,18.211) AR30(-17.291,18.211) AR32(-18.205,18.211) AR33(-19.119,18.211) AR35(-20.034,18.211) AR37(-20.948,18.211) AR38(-21.863,18.211) AR40(-22.777,18.211) AR42(-23.691,18.211) AR43(-24.606,18.211) AR45(-25.52,18.211) AR46(-26.435,18.211) AR48(-27.349,18.211) AR50(-28.263,18.211) AR52(-29.178,18.211) AR53(-30.092,18.211) AR55(-31.007,18.211) AR56(-31.921,18.211) AR58(-32.835,18.211) AR60(-33.75,18.211) AR61(-34.664,18.211) AR63(-35.579,18.211) AR65(-36.493,18.211) AR66(-37.407,18.211) AR68(-38.678,18.26) AR69(-39.328,18.26) AT2(-0.975,18.759) AT4(-1.951,18.759) AT5(-2.66,18.862) AT7(-3.575,18.862) AT8(-4.489,18.862) AT10(-5.403,18.862) AT11(-6.318,18.862) AT13(-7.232,18.862) AT15(-8.147,18.862) AT16(-9.061,18.862) AT18(-9.975,18.862) AT20(-10.89,18.862) AT21(-11.804,18.862) AT22(-12.719,18.862) AT23(-13.633,18.862) AT25(-14.547,18.862) AT27(-15.462,18.862) AT28(-16.376,18.862) AT30(-17.291,18.862) AT32(-18.205,18.862) AT33(-19.119,18.862) AT35(-20.034,18.862) AT37(-20.948,18.862) AT38(-21.863,18.862) AT40(-22.777,18.862) AT42(-23.691,18.862) AT43(-24.606,18.862) AT45(-25.52,18.862) AT46(-26.435,18.862) AT48(-27.349,18.862) AT50(-28.263,18.862) AT52(-29.178,18.862) AT53(-30.092,18.862) AT55(-31.007,18.862) AT56(-31.921,18.862) AT58(-32.835,18.862) AT60(-33.75,18.862) AT61(-34.664,18.862) AT63(-35.579,18.862) AT65(-36.493,18.862) AT66(-37.407,18.862) AT68(-38.353,18.823) AT69(-39.003,18.823) AU4(-1.951,19.422) AU5(-2.66,19.512) AU7(-3.575,19.512) AU8(-4.489,19.512) AU10(-5.403,19.512) AU11(-6.318,19.512) AU13(-7.232,19.512) AU15(-8.147,19.512) AU16(-9.061,19.512) AU18(-9.975,19.512) AU20(-10.89,19.512) AU21(-11.804,19.512) AU22(-12.719,19.512) AU23(-13.633,19.512) AU25(-14.547,19.512) AU27(-15.462,19.512) AU28(-16.376,19.512) AU30(-17.291,19.512) AU32(-18.205,19.512) AU33(-19.119,19.512) AU35(-20.034,19.512) AU37(-20.948,19.512) AU38(-21.863,19.512) AU40(-22.777,19.512) AU42(-23.691,19.512) AU43(-24.606,19.512) AU45(-25.52,19.512) AU46(-26.435,19.512) AU48(-27.349,19.512) AU50(-28.263,19.512) AU52(-29.178,19.512) AU53(-30.092,19.512) AU55(-31.007,19.512) AU56(-31.921,19.512) AU58(-32.835,19.512) AU60(-33.75,19.512) AU61(-34.664,19.512) AU63(-35.579,19.512) AU65(-36.493,19.512) AU66(-37.407,19.512) AV3(-1.626,20.113) AV68(-38.343,20.026) AV69(-39.328,20.215) AV70(-39.978,20.215) AW1(0,20.866) AW5(-2.534,20.226) AW6(-3.184,20.353) AW7(-3.75,20.678) AW8(-4.328,20.353) AW9(-4.898,20.678) AW10(-5.561,20.353) AW11(-6.171,20.678) AW12(-6.749,20.353) AW13(-7.319,20.678) AW14(-7.982,20.353) AW15(-8.592,20.678) AW16(-9.17,20.353) AW17(-9.74,20.678) AW18(-10.403,20.353) AW20(-11.012,20.678) AW21(-11.59,20.353) AW22(-12.16,20.678) AW23(-12.849,20.353) AW25(-13.486,20.678) AW26(-14.05,20.353) AW27(-14.713,20.678) AW28(-15.326,20.353) AW29(-15.94,20.678) AW30(-16.603,20.353) AW31(-17.167,20.678) AW32(-17.83,20.353) AW33(-18.467,20.678) AW34(-19.031,20.353) AW35(-19.694,20.678) AW36(-20.307,20.353) AW37(-20.921,20.678) AW38(-21.584,20.353) AW39(-22.148,20.678) AW41(-22.785,20.353) AW42(-23.423,20.678) AW43(-23.986,20.353) AW44(-24.649,20.678) AW45(-25.263,20.353) AW46(-25.876,20.678) AW47(-26.477,20.353) AW48(-27.041,20.678) AW49(-27.669,20.353) AW50(-28.298,20.678) AW51(-28.862,20.353) AW52(-29.463,20.678) AW53(-30.076,20.353) AW54(-30.69,20.678) AW55(-31.352,20.353) AW56(-31.916,20.678) AW57(-32.554,20.353) AW59(-33.191,20.678) AW60(-33.755,20.353) AW61(-34.418,20.678) AW62(-35.032,20.353) AW63(-35.645,20.678) AW64(-36.308,20.353) AW65(-36.872,20.678) AW66(-37.407,20.215) AW67(-38.332,20.685) AW68(-38.936,20.936) AW69(-39.581,20.85) AW70(-39.999,21.349) AW71(-40.629,20.866) AY2(-0.629,21.348) AY3(-1.286,21.342) AY4(-2.04,21.357) AY5(-2.649,21.003) AY8(-4.328,21.003) AY12(-6.749,21.003) AY16(-9.17,21.003) AY21(-11.59,21.003) AY26(-14.05,21.003) AY27(-14.713,21.328) AY29(-15.94,21.328) AY30(-16.603,21.003) AY34(-19.031,21.003) AY35(-19.694,21.328) AY37(-20.921,21.328) AY38(-21.584,21.003) AY43(-23.986,21.003) AY44(-24.649,21.328) AY46(-25.876,21.328) AY47(-26.477,21.003) AY51(-28.862,21.003) AY52(-29.463,21.328) AY54(-30.69,21.328) AY55(-31.352,21.003) AY60(-33.755,21.003) AY61(-34.418,21.328) AY63(-35.645,21.328) AY64(-36.308,21.003) AY66(-37.535,21.003) AY68(-38.85,21.581) B5(-2.266,0.65) B6(-2.847,0.975) B10(-5.325,0.975) B14(-7.803,0.975) B18(-10.281,0.975) B22(-12.759,0.975) B26(-15.237,0.975) B30(-17.715,0.975) B34(-20.194,0.975) B39(-22.672,0.975) B44(-25.15,0.975) B48(-27.628,0.975) B53(-30.106,0.975) B58(-32.584,0.975) B62(-35.062,0.975) B66(-37.54,0.975) B69(-39.349,0.63) BA3(-1.279,21.999) BA5(-2.599,21.94) BA8(-4.328,21.653) BA12(-6.749,21.653) BA16(-9.17,21.653) BA21(-11.59,21.653) BA23(-12.849,21.572) BA28(-15.326,21.572) BA32(-17.83,21.572) BA36(-20.307,21.572) BA41(-22.785,21.572) BA45(-25.263,21.572) BA49(-27.669,21.653) BA53(-30.076,21.572) BA57(-32.554,21.572) BA62(-35.032,21.572) BA68(-39.349,21.999) BB4(-1.763,22.628) BB68(-38.866,22.628) C4(-1.699,0.978) C5(-2.266,1.3) C7(-3.523,1.3) C8(-4.086,0.975) C9(-4.65,1.3) C11(-6.001,1.3) C12(-6.564,0.975) C13(-7.128,1.3) C15(-8.479,1.3) C16(-9.042,0.975) C17(-9.606,1.3) C19(-10.957,1.3) C20(-11.52,0.975) C21(-12.084,1.3) C23(-13.435,1.3) C24(-13.998,0.975) C25(-14.562,1.3) C27(-15.913,1.3) C28(-16.476,0.975) C29(-17.04,1.3) C31(-18.391,1.3) C32(-18.954,0.975) C33(-19.518,1.3) C36(-20.869,1.3) C37(-21.433,0.975) C38(-21.996,1.3) C40(-23.347,1.3) C41(-23.911,0.975) C42(-24.474,1.3) C45(-25.825,1.3) C46(-26.389,0.975) C47(-26.952,1.3) C50(-28.303,1.3) C51(-28.867,0.975) C52(-29.43,1.3) C54(-30.781,1.3) C55(-31.345,0.975) C56(-31.908,1.3) C59(-33.259,1.3) C60(-33.823,0.975) C61(-34.386,1.3) C63(-35.737,1.3) C64(-36.301,0.975) C65(-36.864,1.3) C67(-38.799,1.015) C68(-38.936,1.693) C70(-39.999,1.28) D3(-0.975,1.706) D4(-1.624,1.646) D5(-2.224,1.951) D6(-2.873,1.991) D7(-3.523,1.951) D8(-4.086,1.626) D9(-4.65,1.951) D10(-5.325,1.991) D11(-6.001,1.951) D12(-6.564,1.626) D13(-7.128,1.951) D14(-7.803,1.991) D15(-8.479,1.951) D16(-9.042,1.626) D17(-9.606,1.951) D18(-10.281,1.991) D19(-10.957,1.951) D20(-11.52,1.626) D21(-12.084,1.951) D22(-12.759,1.991) D23(-13.435,1.951) D24(-13.998,1.626) D25(-14.562,1.951) D26(-15.237,1.991) D27(-15.913,1.951) D28(-16.476,1.626) D29(-17.04,1.951) D30(-17.715,1.991) D31(-18.391,1.951) D32(-18.954,1.626) D33(-19.518,1.951) D34(-20.194,1.991) D36(-20.869,1.951) D37(-21.433,1.626) D38(-21.996,1.951) D39(-22.672,1.991) D40(-23.347,1.951) D41(-23.911,1.626) D42(-24.474,1.951) D44(-25.15,1.991) D45(-25.825,1.951) D46(-26.389,1.626) D47(-26.952,1.951) D48(-27.628,1.991) D50(-28.303,1.951) D51(-28.867,1.626) D52(-29.43,1.951) D53(-30.106,1.991) D54(-30.781,1.951) D55(-31.345,1.626) D56(-31.908,1.951) D58(-32.584,1.991) D59(-33.259,1.951) D60(-33.823,1.626) D61(-34.386,1.951) D62(-35.062,1.991) D63(-35.737,1.951) D64(-36.301,1.626) D65(-36.864,1.951) D66(-37.54,1.991) D67(-38.213,1.3) D68(-39.582,1.779) D69(-38.876,2.343) D71(-40.629,1.763) E1(0,2.274) E2(-0.65,2.274) E3(-1.3,2.274) E5(-2.66,2.723) E6(-3.575,2.723) E8(-4.489,2.723) E10(-5.403,2.723) E11(-6.318,2.723) E13(-7.232,2.723) E15(-8.147,2.723) E16(-9.061,2.723) E18(-9.975,2.723) E20(-10.89,2.723) E21(-11.804,2.723) E22(-12.719,2.723) E23(-13.633,2.723) E25(-14.547,2.723) E27(-15.462,2.723) E28(-16.376,2.723) E30(-17.291,2.723) E32(-18.205,2.723) E33(-19.119,2.723) E35(-20.034,2.723) E37(-20.948,2.723) E38(-21.863,2.723) E40(-22.777,2.723) E42(-23.691,2.723) E43(-24.606,2.723) E45(-25.52,2.723) E46(-26.435,2.723) E48(-27.349,2.723) E50(-28.263,2.723) E52(-29.178,2.723) E53(-30.092,2.723) E55(-31.007,2.723) E56(-31.921,2.723) E58(-32.835,2.723) E60(-33.75,2.723) E61(-34.664,2.723) E63(-35.629,2.659) E65(-36.645,2.659) E66(-37.661,2.659) E68(-38.213,1.951) F2(-0.975,2.848) F4(-1.951,2.848) F5(-2.66,3.373) F6(-3.575,3.373) F8(-4.489,3.373) F10(-5.403,3.373) F11(-6.318,3.373) F13(-7.232,3.373) F15(-8.147,3.373) F16(-9.061,3.373) F18(-9.975,3.373) F20(-10.89,3.373) F21(-11.804,3.373) F22(-12.719,3.373) F23(-13.633,3.373) F25(-14.547,3.373) F27(-15.462,3.373) F28(-16.376,3.373) F30(-17.291,3.373) F32(-18.205,3.373) F33(-19.119,3.373) F35(-20.034,3.373) F37(-20.948,3.373) F38(-21.863,3.373) F40(-22.777,3.373) F42(-23.691,3.373) F43(-24.606,3.373) F45(-25.52,3.373) F46(-26.435,3.373) F48(-27.349,3.373) F50(-28.263,3.373) F52(-29.178,3.373) F53(-30.092,3.373) F55(-31.007,3.373) F56(-31.921,3.373) F58(-32.835,3.373) F60(-33.75,3.373) F61(-34.664,3.373) F63(-35.629,3.31) F65(-36.645,3.31) F66(-37.661,3.31) F68(-38.876,2.994) G4(-1.951,3.511) G5(-2.66,4.023) G6(-3.575,4.023) G8(-4.489,4.023) G10(-5.403,4.023) G11(-6.318,4.023) G13(-7.232,4.023) G15(-8.147,4.023) G16(-9.061,4.023) G18(-9.975,4.023) G20(-10.89,4.023) G21(-11.804,4.023) G22(-12.719,4.023) G23(-13.633,4.023) G25(-14.547,4.023) G27(-15.462,4.023) G28(-16.376,4.023) G30(-17.291,4.023) G32(-18.205,4.023) G33(-19.119,4.023) G35(-20.034,4.023) G37(-20.948,4.023) G38(-21.863,4.023) G40(-22.777,4.023) G42(-23.691,4.023) G43(-24.606,4.023) G45(-25.52,4.023) G46(-26.435,4.023) G48(-27.349,4.023) G50(-28.263,4.023) G52(-29.178,4.023) G53(-30.092,4.023) G55(-31.007,4.023) G56(-31.921,4.023) G58(-32.835,4.023) G60(-33.75,4.023) G61(-34.664,4.023) G63(-35.629,3.96) G65(-36.645,3.96) G66(-37.661,3.96) G68(-38.678,3.655) G69(-39.328,3.655) H3(-1.626,4.174) H5(-2.66,4.674) H6(-3.575,4.674) H8(-4.489,4.674) H10(-5.403,4.674) H11(-6.318,4.674) H13(-7.232,4.674) H15(-8.147,4.674) H16(-9.061,4.674) H18(-9.975,4.674) H20(-10.89,4.674) H21(-11.804,4.674) H63(-35.629,4.61) H65(-36.645,4.61) H66(-37.661,4.61) H69(-39.003,4.218) J4(-1.951,4.837) J5(-2.66,5.324) J6(-3.575,5.324) J8(-4.489,5.324) J10(-5.403,5.324) J11(-6.318,5.324) J13(-7.232,5.324) J22(-13.176,4.488) J23(-14.09,4.488) J25(-15.005,4.488) J27(-15.919,4.488) J28(-16.833,4.488) J30(-17.748,4.488) J32(-18.662,4.488) J33(-19.577,4.488) J35(-20.491,4.488) J37(-21.405,4.488) J38(-22.32,4.488) J40(-23.234,4.488) J42(-24.149,4.488) J43(-25.063,4.488) J45(-25.977,4.488) J46(-26.892,4.488) J48(-27.806,4.488) J50(-28.721,4.488) J52(-29.635,4.488) J53(-30.549,4.488) J55(-31.464,4.488) J56(-32.378,4.488) J58(-33.293,4.488) J60(-34.207,4.488) J68(-38.676,4.794) K15(-8.126,5.438) K16(-8.776,5.438) K17(-9.426,5.438) K18(-10.077,5.438) K19(-10.727,5.438) K20(-11.377,5.438) K21(-12.027,5.438) K22(-12.719,4.952) K23(-13.633,4.952) K25(-14.547,4.952) K27(-15.462,4.952) K28(-16.376,4.952) K30(-17.291,4.952) K32(-18.205,4.952) K33(-19.119,4.952) K35(-20.034,4.952) K37(-20.948,4.952) K38(-21.863,4.952) K40(-22.777,4.952) K42(-23.691,4.952) K43(-24.606,4.952) K45(-25.52,4.952) K46(-26.435,4.952) K48(-27.349,4.952) K50(-28.263,4.952) K52(-29.178,4.952) K53(-30.092,4.952) K55(-31.007,4.952) K56(-31.921,4.952) K58(-32.835,4.952) K60(-33.75,4.952) K61(-34.664,4.952) K63(-35.447,5.26) K64(-36.097,5.26) K65(-36.747,5.26) K66(-37.398,5.26) K67(-38.048,5.26) K68(-38.666,5.468) K70(-39.653,5.57) L2(-0.975,5.5) L4(-1.951,5.5) L6(-2.729,5.974) L7(-3.379,5.974) L8(-4.029,5.974) L9(-4.679,5.974) L10(-5.33,5.974) L11(-5.98,5.974) L12(-6.63,5.974) L13(-7.28,5.974) L15(-8.126,6.276) L16(-8.776,6.276) L17(-9.426,6.276) L18(-10.077,6.276) L19(-10.727,6.276) L20(-11.377,6.276) L21(-12.027,6.276) L62(-34.958,5.689) L63(-35.427,6.147) L64(-36.077,6.147) L65(-36.727,6.147) L66(-37.377,6.147) L67(-38.028,6.147) L68(-38.678,6.147) L69(-39.328,6.147) L70(-39.978,6.147) L71(-40.629,6.147) M4(-1.951,6.163) M62(-34.958,6.604) N3(-1.626,6.826) N6(-2.729,6.914) N7(-3.379,6.914) N8(-4.029,6.914) N9(-4.679,6.914) N10(-5.33,6.914) N11(-5.98,6.914) N12(-6.63,6.914) N13(-7.28,6.914) N15(-8.126,7.114) N16(-8.776,7.114) N17(-9.426,7.114) N18(-10.077,7.114) N19(-10.727,7.114) N20(-11.377,7.114) N21(-12.027,7.114) N63(-35.427,7.061) N64(-36.077,7.061) N65(-36.727,7.061) N66(-37.377,7.061) N67(-38.028,7.061) N68(-38.678,7.061) N69(-39.328,7.061) N70(-39.978,7.061) N71(-40.629,7.061) P4(-1.951,7.489) P15(-8.126,7.952) P16(-8.776,7.952) P17(-9.426,7.952) P18(-10.077,7.952) P19(-10.727,7.952) P20(-11.377,7.952) P21(-12.027,7.952) P62(-34.958,7.518) R6(-2.729,7.981) R7(-3.379,7.981) R8(-4.029,7.981) R9(-4.679,7.981) R10(-5.33,7.981) R11(-5.98,7.981) R12(-6.63,7.981) R13(-7.28,7.981) R63(-35.427,7.975) R64(-36.077,7.975) R65(-36.727,7.975) R66(-37.377,7.975) R67(-38.028,7.975) R68(-38.678,7.975) R69(-39.328,7.975) R70(-39.978,7.975) R71(-40.629,7.975) T2(-0.975,8.152) T4(-1.951,8.152) T15(-8.126,8.791) T16(-8.776,8.791) T17(-9.426,8.791) T18(-10.077,8.791) T19(-10.727,8.791) T20(-11.377,8.791) T21(-12.027,8.791) T62(-34.958,8.433) U4(-1.951,8.815) U6(-2.729,9.047) U7(-3.379,9.047) U8(-4.029,9.047) U9(-4.679,9.047) U10(-5.33,9.047) U11(-5.98,9.047) U12(-6.63,9.047) U13(-7.28,9.047) U63(-35.427,8.89) U64(-36.077,8.89) U65(-36.727,8.89) U66(-37.377,8.89) U67(-38.028,8.89) U68(-38.678,8.89) U69(-39.328,8.89) U70(-39.978,8.89) U71(-40.629,8.89) V3(-1.626,9.478) V15(-8.126,9.629) V16(-8.776,9.629) V17(-9.426,9.629) V18(-10.077,9.629) V19(-10.727,9.629) V20(-11.377,9.629) V21(-12.027,9.629) V62(-34.958,9.347) W4(-1.951,10.141) W6(-2.729,10.114) W7(-3.379,10.114) W8(-4.029,10.114) W9(-4.679,10.114) W10(-5.33,10.114) W11(-5.98,10.114) W12(-6.63,10.114) W13(-7.28,10.114) W63(-35.427,9.804) W64(-36.077,9.804) W65(-36.727,9.804) W66(-37.377,9.804) W67(-38.028,9.804) W68(-38.678,9.804) W69(-39.328,9.804) W70(-39.978,9.804) W71(-40.629,9.804) Y15(-8.126,10.467) Y16(-8.776,10.467) Y17(-9.426,10.467) Y18(-10.077,10.467) Y19(-10.727,10.467) Y20(-11.377,10.467) Y21(-12.027,10.467) Y62(-34.958,10.261)
  oval 0.254x0.343 smd: A6(-2.847,0.325) A7(-3.523,0) A9(-4.65,0) A10(-5.325,0.325) A11(-6.001,0) A13(-7.128,0) A14(-7.803,0.325) A15(-8.479,0) A17(-9.606,0) A18(-10.281,0.325) A19(-10.957,0) A21(-12.084,0) A22(-12.759,0.325) A23(-13.435,0) A25(-14.562,0) A26(-15.237,0.325) A27(-15.913,0) A29(-17.04,0) A30(-17.715,0.325) A31(-18.391,0) A33(-19.518,0) A34(-20.194,0.325) A36(-20.869,0) A38(-21.996,0) A39(-22.672,0.325) A40(-23.347,0) A42(-24.474,0) A44(-25.15,0.325) A45(-25.825,0) A47(-26.952,0) A48(-27.628,0.325) A50(-28.303,0) A52(-29.43,0) A53(-30.106,0.325) A54(-30.781,0) A56(-31.908,0) A58(-32.584,0.325) A59(-33.259,0) A61(-34.386,0) A62(-35.062,0.325) A63(-35.737,0) A65(-36.864,0) A66(-37.54,0.325) A67(-38.215,0) AY7(-3.763,21.328) AY9(-4.898,21.328) AY11(-6.184,21.328) AY13(-7.319,21.328) AY15(-8.604,21.328) AY17(-9.74,21.328) AY20(-11.025,21.328) AY22(-12.16,21.328) AY25(-13.486,21.328) AY31(-17.167,21.328) AY33(-18.467,21.328) AY39(-22.148,21.328) AY42(-23.423,21.328) AY48(-27.103,21.328) AY50(-28.236,21.328) AY56(-31.916,21.328) AY59(-33.191,21.328) AY65(-36.872,21.328) AY67(-38.216,21.328) B7(-3.523,0.65) B9(-4.65,0.65) B11(-6.001,0.65) B13(-7.128,0.65) B15(-8.479,0.65) B17(-9.606,0.65) B19(-10.957,0.65) B21(-12.084,0.65) B23(-13.435,0.65) B25(-14.562,0.65) B27(-15.913,0.65) B29(-17.04,0.65) B31(-18.391,0.65) B33(-19.518,0.65) B36(-20.869,0.65) B38(-21.996,0.65) B40(-23.347,0.65) B42(-24.474,0.65) B45(-25.825,0.65) B47(-26.952,0.65) B50(-28.303,0.65) B52(-29.43,0.65) B54(-30.781,0.65) B56(-31.908,0.65) B59(-33.259,0.65) B61(-34.386,0.65) B63(-35.737,0.65) B65(-36.864,0.65) B67(-38.215,0.65) BA4(-1.948,22.004) BA6(-3.141,21.572) BA7(-3.705,21.978) BA9(-4.898,21.978) BA10(-5.561,21.572) BA11(-6.125,21.978) BA13(-7.319,21.978) BA14(-7.982,21.572) BA15(-8.546,21.978) BA17(-9.74,21.978) BA18(-10.403,21.572) BA20(-10.966,21.978) BA22(-12.16,21.978) BA25(-13.486,21.978) BA26(-14.149,21.653) BA27(-14.812,21.978) BA29(-15.841,21.978) BA30(-16.504,21.653) BA31(-17.167,21.978) BA33(-18.467,21.978) BA34(-19.13,21.653) BA35(-19.793,21.978) BA37(-20.822,21.978) BA38(-21.485,21.653) BA39(-22.148,21.978) BA42(-23.423,21.978) BA43(-24.086,21.653) BA44(-24.748,21.978) BA46(-25.777,21.978) BA47(-26.44,21.653) BA48(-27.103,21.978) BA50(-28.236,21.978) BA51(-28.899,21.653) BA52(-29.562,21.978) BA54(-30.59,21.978) BA55(-31.253,21.653) BA56(-31.916,21.978) BA59(-33.191,21.978) BA60(-33.854,21.653) BA61(-34.517,21.978) BA63(-35.546,21.978) BA64(-36.209,21.653) BA65(-36.872,21.978) BA66(-37.535,21.653) BA67(-38.216,21.978) BB5(-2.529,22.628) BB6(-3.141,22.303) BB7(-3.705,22.628) BB9(-4.898,22.628) BB10(-5.561,22.303) BB11(-6.125,22.628) BB13(-7.319,22.628) BB14(-7.982,22.303) BB15(-8.546,22.628) BB17(-9.74,22.628) BB18(-10.403,22.303) BB20(-10.966,22.628) BB22(-12.16,22.628) BB23(-12.849,22.222) BB25(-13.486,22.628) BB26(-14.149,22.303) BB27(-14.812,22.628) BB29(-15.841,22.628) BB30(-16.504,22.303) BB31(-17.167,22.628) BB32(-17.83,22.222) BB33(-18.467,22.628) BB34(-19.13,22.303) BB35(-19.793,22.628) BB37(-20.822,22.628) BB38(-21.485,22.303) BB39(-22.148,22.628) BB41(-22.785,22.222) BB42(-23.423,22.628) BB43(-24.086,22.303) BB44(-24.748,22.628) BB46(-25.777,22.628) BB47(-26.44,22.303) BB48(-27.103,22.628) BB50(-28.236,22.628) BB51(-28.899,22.303) BB52(-29.562,22.628) BB54(-30.59,22.628) BB55(-31.253,22.303) BB56(-31.916,22.628) BB57(-32.554,22.222) BB59(-33.191,22.628) BB60(-33.854,22.303) BB61(-34.517,22.628) BB63(-35.546,22.628) BB64(-36.209,22.303) BB65(-36.872,22.628) BB66(-37.535,22.303) BB67(-38.216,22.628)
  oval 0.343x0.254 smd: AA1(-0.325,10.804) AB1(0,11.467) AB2(-0.65,11.467) AB3(-1.3,11.467) AC1(-0.325,12.13) AC2(-0.975,12.13) AD1(0,12.792) AD2(-0.65,12.792) AD3(-1.3,12.792) AF1(-0.325,13.455) AF70(-39.978,13.154) AF71(-40.629,13.154) AG1(0,14.118) AG2(-0.65,14.118) AG3(-1.3,14.118) AG70(-39.653,13.817) AG71(-40.303,13.817) AH1(-0.325,14.781) AH2(-0.975,14.781) AH68(-38.678,14.48) AH69(-39.328,14.48) AH70(-39.978,14.48) AH71(-40.629,14.48) AJ1(0,15.444) AJ2(-0.65,15.444) AJ3(-1.3,15.444) AK70(-40.303,15.143) AL1(-0.325,16.107) AL68(-38.678,15.806) AL69(-39.328,15.806) AL70(-39.978,15.806) AL71(-40.629,15.806) AM1(0,16.77) AM2(-0.65,16.77) AM3(-1.3,16.77) AM70(-39.653,16.469) AM71(-40.303,16.469) AN1(-0.325,17.433) AN2(-0.975,17.433) AN70(-39.978,17.132) AN71(-40.629,17.132) AP1(0,18.096) AP2(-0.65,18.096) AP3(-1.3,18.096) AR70(-39.978,18.16) AR71(-40.629,18.16) AT1(-0.325,18.759) AT70(-39.653,18.823) AT71(-40.303,18.823) AU1(0,19.422) AU2(-0.65,19.422) AU3(-1.3,19.422) AU68(-38.678,19.461) AU69(-39.328,19.486) AU70(-39.978,19.486) AU71(-40.629,19.486) AV1(0,20.142) AV2(-0.95,20.113) AV71(-40.629,20.215) AW2(-0.625,20.677) AW3(-1.275,20.677) E70(-39.978,2.305) E71(-40.629,2.413) F1(-0.325,2.848) F70(-39.526,2.994) F71(-40.176,2.931) G1(0,3.511) G2(-0.65,3.511) G3(-1.3,3.511) G70(-39.978,3.555) G71(-40.629,3.555) H1(-0.325,4.174) H2(-0.975,4.174) H70(-39.653,4.218) H71(-40.303,4.218) J1(0,4.837) J2(-0.65,4.837) J3(-1.3,4.837) J69(-39.328,4.881) J70(-39.978,4.881) J71(-40.629,4.881) K71(-40.303,5.57) L1(-0.325,5.5) M1(0,6.163) M2(-0.65,6.163) M3(-1.3,6.163) N1(-0.325,6.826) N2(-0.975,6.826) P1(0,7.489) P2(-0.65,7.489) P3(-1.3,7.489) T1(-0.325,8.152) U1(0,8.815) U2(-0.65,8.815) U3(-1.3,8.815) V1(-0.325,9.478) V2(-0.975,9.478) W1(0,10.141) W2(-0.65,10.141) W3(-1.3,10.141)
